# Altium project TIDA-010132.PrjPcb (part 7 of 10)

## Sheet USB INTERFACE SHEET.SchDoc
size 558 x 431 mm; Date: Not shown in title block; ApprovedBy: Not shown in title block; CheckedBy: Not shown in title block; Author: Not shown in title block; CompanyName: Not shown in title block; DrawnBy: Avinash N; Engineer: Not shown in title block; Organization: Not shown in title block; Address1: Not shown in title block; Address2: Not shown in title block; Address3: Not shown in title block; Address4: Not shown in title block; DocumentNumber: 1; Revision: Use project parameter SCH_Rev; SheetNumber: 27; SheetTotal: 32; PageSetup: Record=PageOptions¦CenterHorizontal=True¦CenterVertical=True¦PrintScale=1.00¦XCorrection=1.00¦YCorrection=1.00¦PrintKind=0¦BorderSize=5000000¦LeftOffset=0¦BottomOffset=0¦Orientation=2¦PaperLength=1000¦PaperWidth=1000¦Scale=100¦PaperSource=15¦PrintQuality=600¦MediaType=1¦DitherType=10¦PaperKind=Letter¦PrintScaleMode=1
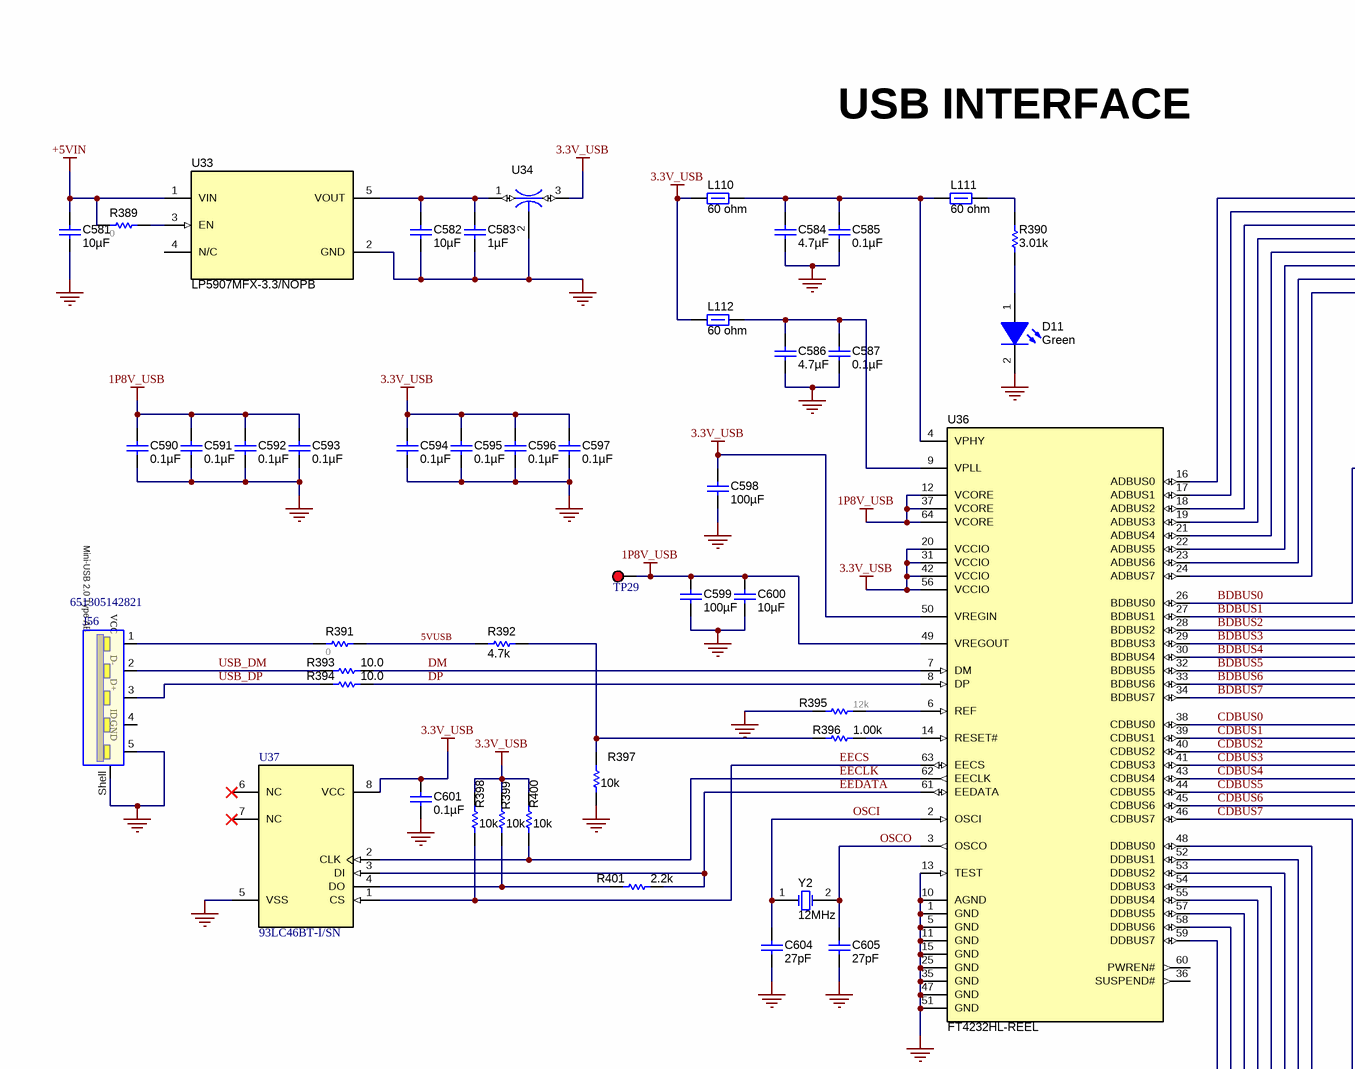
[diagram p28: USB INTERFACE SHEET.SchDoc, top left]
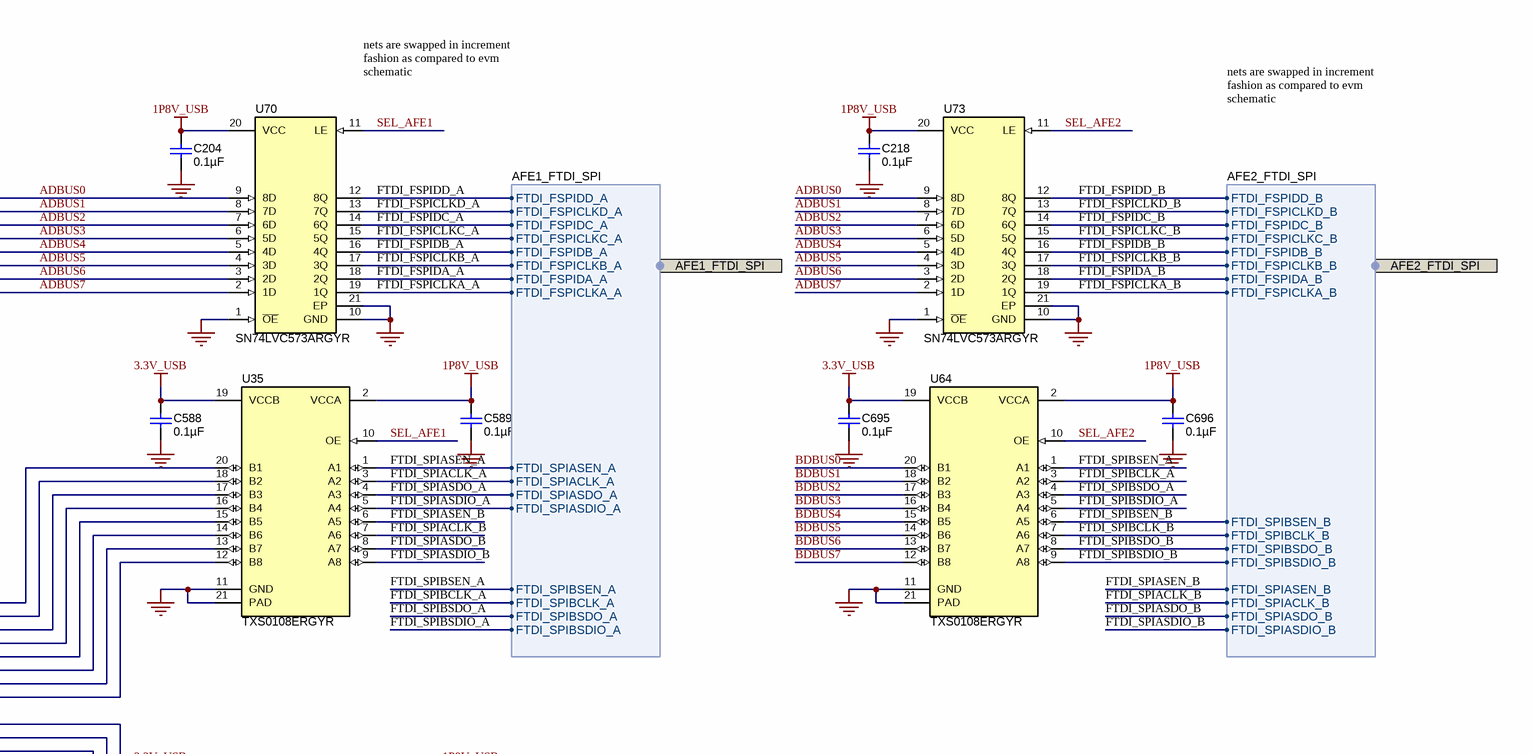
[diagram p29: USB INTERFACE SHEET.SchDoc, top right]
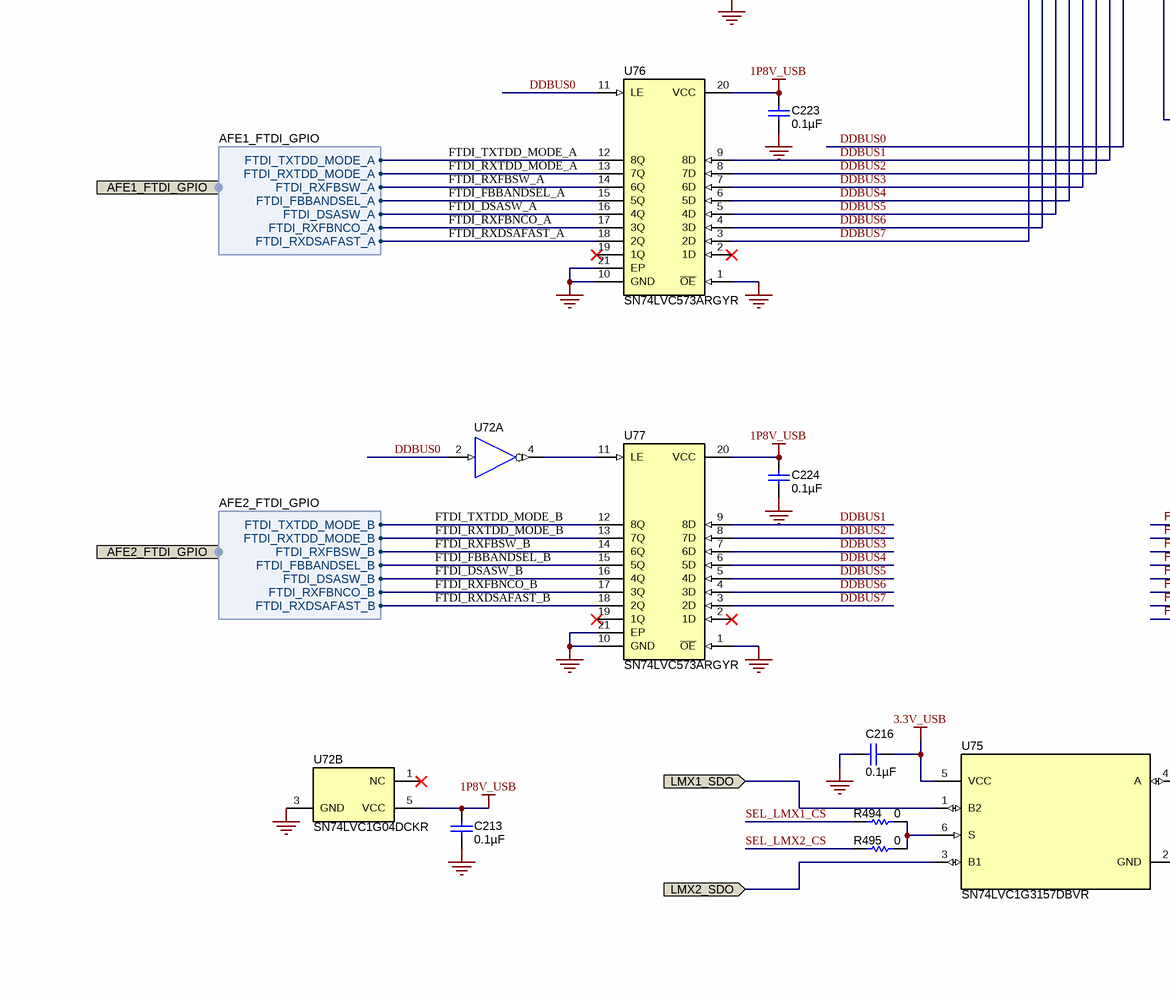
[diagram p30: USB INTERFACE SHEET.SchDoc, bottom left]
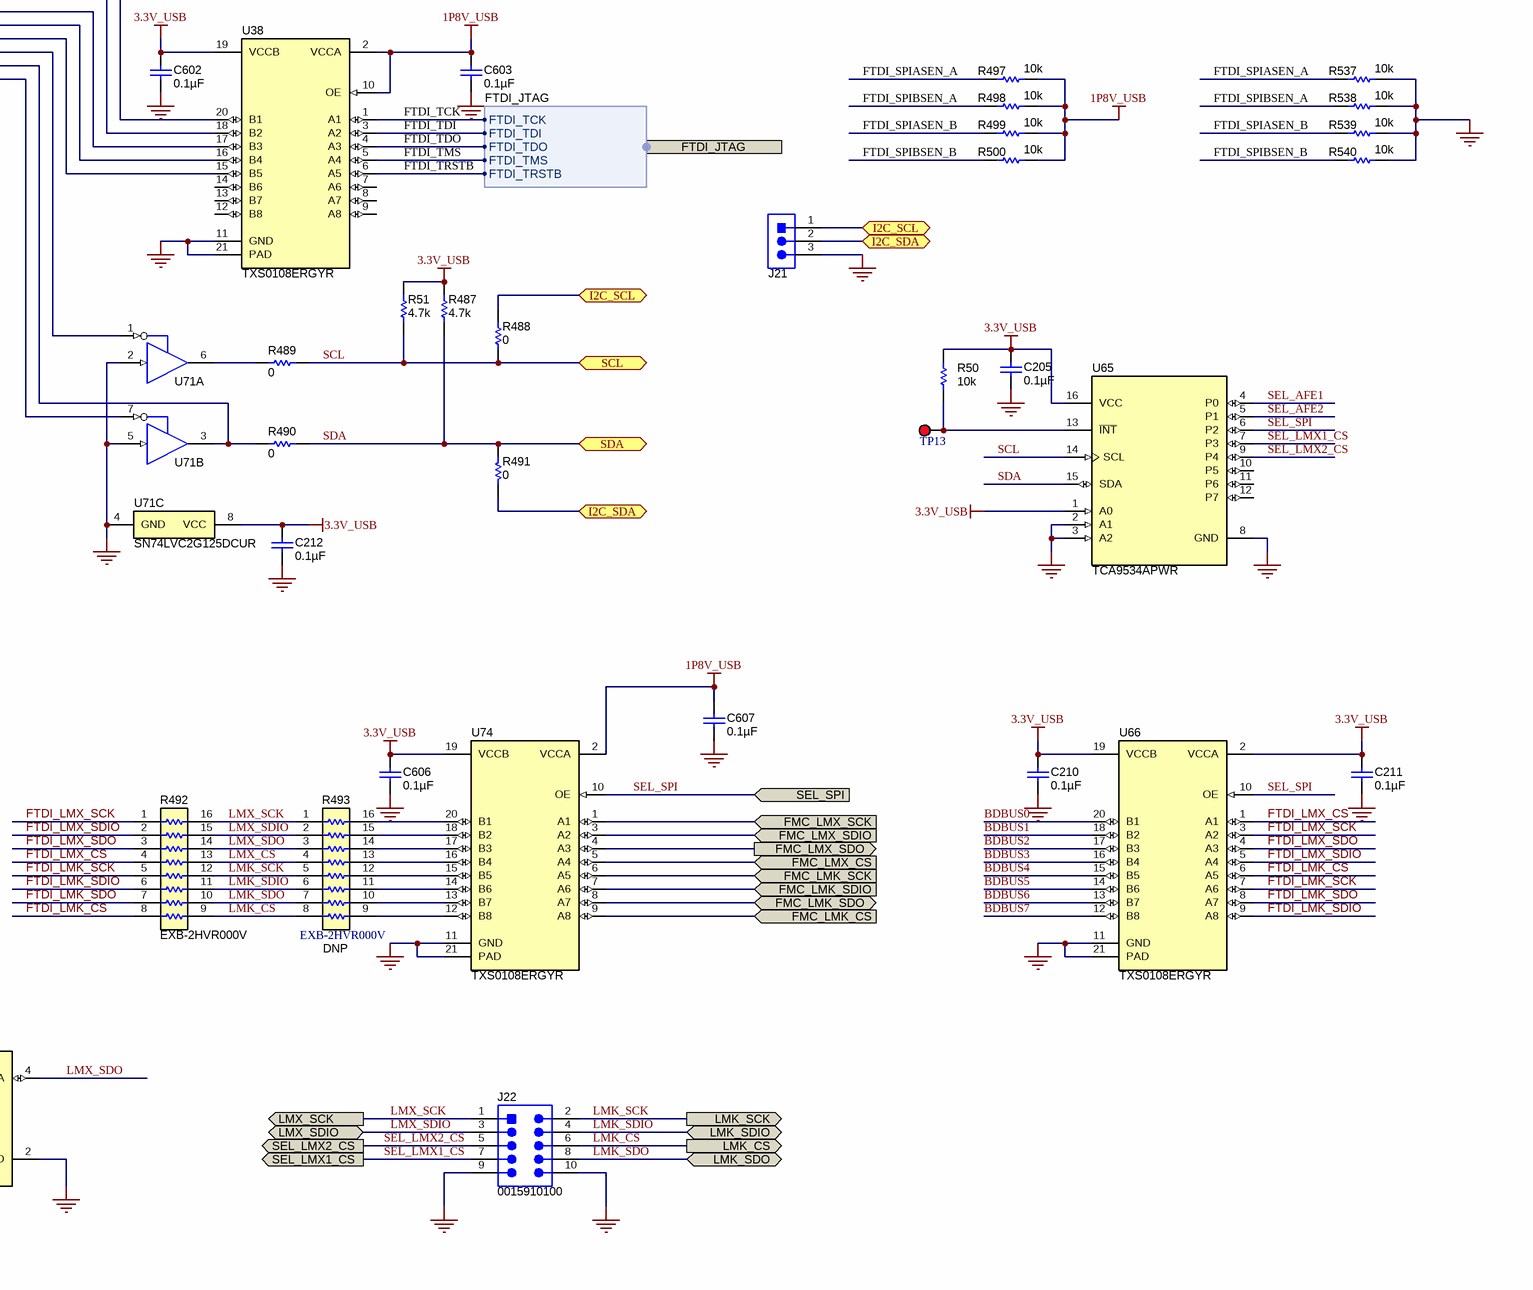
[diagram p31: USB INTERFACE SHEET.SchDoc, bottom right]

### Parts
C204  ValueDisplayed: 0.1µF  [0603]  (hidden comment: C0603C104J3RACTU)
C205  ValueDisplayed: 0.1µF  [0603]  (hidden comment: C0603C104J3RACTU)
C210  ValueDisplayed: 0.1µF  [0603]  (hidden comment: C0603C104J3RACTU)
C211  ValueDisplayed: 0.1µF  [0603]  (hidden comment: C0603C104J3RACTU)
C212  ValueDisplayed: 0.1µF  [0603]  (hidden comment: C0603C104J3RACTU)
C213  ValueDisplayed: 0.1µF  [0603]  (hidden comment: C0603C104J3RACTU)
C216  ValueDisplayed: 0.1µF  [0603]  (hidden comment: C0603C104J3RACTU)
C218  ValueDisplayed: 0.1µF  [0603]  (hidden comment: C0603C104J3RACTU)
C223  ValueDisplayed: 0.1µF  [0603]  (hidden comment: C0603C104J3RACTU)
C224  ValueDisplayed: 0.1µF  [0603]  (hidden comment: C0603C104J3RACTU)
C581  ValueDisplayed: 10µF  [0603]  (hidden comment: GRM188R61A106ME69D)
C582  ValueDisplayed: 10µF  [0603]  (hidden comment: GRM188R61A106ME69D)
C583  ValueDisplayed: 1µF  [0603]  (hidden comment: C1608X7R1C105K080AC)
C584  ValueDisplayed: 4.7µF  [0805_HV]  (hidden comment: 885012207025)
C585  ValueDisplayed: 0.1µF  [0603]  (hidden comment: C0603C104J3RACTU)
C586  ValueDisplayed: 4.7µF  [0805_HV]  (hidden comment: 885012207025)
C587  ValueDisplayed: 0.1µF  [0603]  (hidden comment: C0603C104J3RACTU)
C588  ValueDisplayed: 0.1µF  [0603]  (hidden comment: C0603C104J3RACTU)
C589  ValueDisplayed: 0.1µF  [0603]  (hidden comment: C0603C104J3RACTU)
C590  ValueDisplayed: 0.1µF  [0603]  (hidden comment: C0603C104J3RACTU)
C591  ValueDisplayed: 0.1µF  [0603]  (hidden comment: C0603C104J3RACTU)
C592  ValueDisplayed: 0.1µF  [0603]  (hidden comment: C0603C104J3RACTU)
C593  ValueDisplayed: 0.1µF  [0603]  (hidden comment: C0603C104J3RACTU)
C594  ValueDisplayed: 0.1µF  [0603]  (hidden comment: C0603C104J3RACTU)
C595  ValueDisplayed: 0.1µF  [0603]  (hidden comment: C0603C104J3RACTU)
C596  ValueDisplayed: 0.1µF  [0603]  (hidden comment: C0603C104J3RACTU)
C597  ValueDisplayed: 0.1µF  [0603]  (hidden comment: C0603C104J3RACTU)
C598  ValueDisplayed: 100µF  [1210_270]  (hidden comment: GRM32ER61A107ME20L)
C599  ValueDisplayed: 100µF  [1210_270]  (hidden comment: GRM32ER61A107ME20L)
C600  ValueDisplayed: 10µF  [0603]  (hidden comment: GRM188R61A106ME69D)
C601  ValueDisplayed: 0.1µF  [0603]  (hidden comment: C0603C104J3RACTU)
C602  ValueDisplayed: 0.1µF  [0603]  (hidden comment: C0603C104J3RACTU)
C603  ValueDisplayed: 0.1µF  [0603]  (hidden comment: C0603C104J3RACTU)
C604  ValueDisplayed: 27pF  [0603]  (hidden comment: CL10C270FB8NNNC)
C605  ValueDisplayed: 27pF  [0603]  (hidden comment: CL10C270FB8NNNC)
C606  ValueDisplayed: 0.1µF  [0603]  (hidden comment: C0603C104J3RACTU)
C607  ValueDisplayed: 0.1µF  [0603]  (hidden comment: C0603C104J3RACTU)
C695  ValueDisplayed: 0.1µF  [0603]  (hidden comment: C0603C104J3RACTU)
C696  ValueDisplayed: 0.1µF  [0603]  (hidden comment: C0603C104J3RACTU)
D11  value Green  [LTST-C191_Green]  (hidden comment: LTST-C191TGKT)
J21  800-10-003-10-001000  [Mill-Max_800-10-003-10-001000]  (value not drawn)
J22  0015910100  [Molex_0015910100]
J56  651305142821  [651305142821]
L110  ValueDisplayed: 60 ohm  [0603]  (hidden comment: MPZ1608S600ATAH0)
L111  ValueDisplayed: 60 ohm  [0603]  (hidden comment: MPZ1608S600ATAH0)
L112  ValueDisplayed: 60 ohm  [0603]  (hidden comment: MPZ1608S600ATAH0)
R50  ValueDisplayed: 10k  [0603]  (hidden comment: CRCW060310K0JNEA)
R51  ValueDisplayed: 4.7k  [0603]  (hidden comment: CRCW06034K70JNEA)
R389  value 0  [0603]  (hidden comment: CRCW06030000Z0EA)
R390  ValueDisplayed: 3.01k  [0603]  (hidden comment: RC0603FR-073K01L)
R391  value 0  [0603]  (hidden comment: CRCW06030000Z0EA)
R392  ValueDisplayed: 4.7k  [0603]  (hidden comment: RC0603JR-074K7L)
R393  ValueDisplayed: 10.0  [0603]  (hidden comment: CRCW060310R0FKEAHP)
R394  ValueDisplayed: 10.0  [0603]  (hidden comment: CRCW060310R0FKEAHP)
R395  value 12k  [0603]  (hidden comment: CRCW060312K0JNEA)
R396  ValueDisplayed: 1.00k  [0603]  (hidden comment: CRCW06031K00FKEA)
R397  ValueDisplayed: 10k  [0603]  (hidden comment: CRCW060310K0JNEA)
R398  ValueDisplayed: 10k  [0603]  (hidden comment: CRCW060310K0JNEA)
R399  ValueDisplayed: 10k  [0603]  (hidden comment: CRCW060310K0JNEA)
R400  ValueDisplayed: 10k  [0603]  (hidden comment: CRCW060310K0JNEA)
R401  ValueDisplayed: 2.2k  [0603]  (hidden comment: CRCW06032K20JNEA)
R487  ValueDisplayed: 4.7k  [0603]  (hidden comment: CRCW06034K70JNEA)
R488  ValueDisplayed: 0  [0603]  (hidden comment: CRCW06030000Z0EA)
R489  ValueDisplayed: 0  [0603]  (hidden comment: CRCW06030000Z0EA)
R490  ValueDisplayed: 0  [0603]  (hidden comment: CRCW06030000Z0EA)
R491  ValueDisplayed: 0  [0603]  (hidden comment: CRCW06030000Z0EA)
R492  EXB-2HVR000V  [RESCAXS_EXB-2HV]
R493  DNP  PartNumber: EXB-2HVR000V  [RESCAXS_EXB-2HV]
R494  ValueDisplayed: 0  [0603]  (hidden comment: CRCW06030000Z0EA)
R495  ValueDisplayed: 0  [0603]  (hidden comment: CRCW06030000Z0EA)
R497  ValueDisplayed: 10k  [0603]  (hidden comment: CRCW060310K0JNEA)
R498  ValueDisplayed: 10k  [0603]  (hidden comment: CRCW060310K0JNEA)
R499  ValueDisplayed: 10k  [0603]  (hidden comment: CRCW060310K0JNEA)
R500  ValueDisplayed: 10k  [0603]  (hidden comment: CRCW060310K0JNEA)
R537  ValueDisplayed: 10k  [0603]  (hidden comment: CRCW060310K0JNEA)
R538  ValueDisplayed: 10k  [0603]  (hidden comment: CRCW060310K0JNEA)
R539  ValueDisplayed: 10k  [0603]  (hidden comment: CRCW060310K0JNEA)
R540  ValueDisplayed: 10k  [0603]  (hidden comment: CRCW060310K0JNEA)
TP13  5000  [Keystone5000]  (value not drawn)
TP29  5000  [Keystone5000]  (value not drawn)
U33  LP5907MFX-3.3/NOPB  [DBV0005A_N]
U34  NFM31PC276B0J3L  [Murata_NFM31P]  (value not drawn)
U35  TXS0108ERGYR  [RGY0020A]
U36  FT4232HL-REEL  [LQFP64_N]
U37  93LC46BT-I/SN  [SOIC-8]
U38  TXS0108ERGYR  [RGY0020A]
U64  TXS0108ERGYR  [RGY0020A]
U65  TCA9534APWR  [PW0016A_N]
U66  TXS0108ERGYR  [RGY0020A]
U70  SN74LVC573ARGYR  [RGY0020A]
U71  SN74LVC2G125DCUR  [DCU0008A_N]  (value not drawn)  (parts A,B,C of 3)
U72  SN74LVC1G04DCKR  [DCK0005A_N]  (value not drawn)  (parts A,B of 2)
U73  SN74LVC573ARGYR  [RGY0020A]
U74  TXS0108ERGYR  [RGY0020A]
U75  SN74LVC1G3157DBVR  [DBV0006A_N]
U76  SN74LVC573ARGYR  [RGY0020A]
U77  SN74LVC573ARGYR  [RGY0020A]
Y2  Frequency: 12MHz  [XTAL_ABM3]  (hidden comment: ABM3-12.000MHZ-D2Y-T)

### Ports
AFE1_FTDI_GPIO (harness AFE1_FTDI_GPIO), AFE1_FTDI_SPI (harness AFE1_FTDI_SPI), AFE2_FTDI_GPIO (harness AFE2_FTDI_GPIO), AFE2_FTDI_SPI (harness AFE2_FTDI_SPI), FMC_LMK_CS (in), FMC_LMK_SCK (in), FMC_LMK_SDIO (in), FMC_LMK_SDO (bidir), FMC_LMX_CS (in), FMC_LMX_SCK (in), FMC_LMX_SDIO (in), FMC_LMX_SDO (out), FTDI_JTAG (harness FTDI_JTAG), I2C_SCL (bidir), I2C_SDA (bidir), LMK_CS (out), LMK_SCK (out), LMK_SDIO (bidir), LMK_SDO (bidir), LMX1_SDO (in), LMX2_SDO (in), LMX_SCK (out), LMX_SDIO (bidir), SCL (bidir), SDA (bidir), SEL_LMX1_CS (out), SEL_LMX2_CS (out), SEL_SPI (in)

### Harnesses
AFE2_FTDI_GPIO: FTDI_FBBANDSEL_B, FTDI_RXFBSW_B, FTDI_RXTDD_MODE_B, FTDI_TXTDD_MODE_B, FTDI_DSASW_B, FTDI_RXFBNCO_B, FTDI_RXDSAFAST_B
AFE1_FTDI_GPIO: FTDI_FBBANDSEL_A, FTDI_RXFBSW_A, FTDI_RXTDD_MODE_A, FTDI_TXTDD_MODE_A, FTDI_DSASW_A, FTDI_RXFBNCO_A, FTDI_RXDSAFAST_A
FTDI_JTAG: FTDI_TCK, FTDI_TDI, FTDI_TDO, FTDI_TMS, FTDI_TRSTB
AFE1_FTDI_SPI: FTDI_FSPICLKA_A, FTDI_FSPIDA_A, FTDI_FSPICLKB_A, FTDI_FSPIDB_A, FTDI_FSPICLKC_A, FTDI_FSPIDC_A, FTDI_FSPICLKD_A, FTDI_FSPIDD_A, FTDI_SPIASEN_A, FTDI_SPIACLK_A, FTDI_SPIASDO_A, FTDI_SPIASDIO_A, FTDI_SPIBSEN_A, FTDI_SPIBCLK_A, FTDI_SPIBSDO_A, FTDI_SPIBSDIO_A
AFE2_FTDI_SPI: FTDI_FSPICLKA_B, FTDI_FSPIDA_B, FTDI_FSPICLKB_B, FTDI_FSPIDB_B, FTDI_FSPICLKC_B, FTDI_FSPIDC_B, FTDI_FSPICLKD_B, FTDI_FSPIDD_B, FTDI_SPIASEN_B, FTDI_SPIACLK_B, FTDI_SPIASDO_B, FTDI_SPIASDIO_B, FTDI_SPIBSEN_B, FTDI_SPIBCLK_B, FTDI_SPIBSDO_B, FTDI_SPIBSDIO_B

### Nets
1P8V_USB: C204.2 C213.2 C218.2 C223.2 C224.2 C589.2 C590.2 C591.2 C592.2 C593.2 C599.1 C600.1 C603.2 C607.2 C696.2 R497.1 R498.1 R499.1 R500.1 TP29.1 U35.2(VCCA) U36.12(VCORE) U36.37(VCORE) U36.49(VREGOUT) U36.64(VCORE) U38.2(VCCA) U38.10(OE) U64.2(VCCA) U70.20(VCC) U72.5(VCC) U73.20(VCC) U74.2(VCCA) U76.20(VCC) U77.20(VCC)
3.3V_USB: C205.2 C210.2 C211.2 C212.2 C216.1 C588.2 C594.2 C595.2 C596.2 C597.2 C598.1 C601.2 C602.2 C606.2 C695.2 L110.1 L112.1 R50.2 R51.2 R398.2 R399.2 R400.2 R487.2 U34.3 U35.19(VCCB) U36.20(VCCIO) U36.31(VCCIO) U36.42(VCCIO) U36.50(VREGIN) U36.56(VCCIO) U37.8(VCC) U38.19(VCCB) U64.19(VCCB) U65.1(A0) U65.16(VCC) U66.2(VCCA) U66.19(VCCB) U71.8(VCC) U74.19(VCCB) U75.5(VCC)
+5VIN: C581.1 R389.1 U33.1(VIN)
GND: C204.1 C205.1 C210.1 C211.1 C212.1 C213.1 C216.2 C218.1 C223.1 C224.1 C581.2 C582.2 C583.2 C584.2 C585.1 C586.2 C587.1 C588.1 C589.1 C590.1 C591.1 C592.1 C593.1 C594.1 C595.1 C596.1 C597.1 C598.2 C599.2 C600.2 C601.1 C602.1 C603.1 C604.2 C605.2 C606.1 C607.1 C695.1 C696.1 D11.2(K) J21.3 J22.9 J22.10 J56.5(GND) J56.Shell R395.2 R397.1 R537.1 R538.1 R539.1 R540.1 U33.2(GND) U34.2 U35.11(GND) U35.21(PAD) U36.1(GND) U36.5(GND) U36.10(AGND) U36.11(GND) U36.13(TEST) U36.15(GND) U36.25(GND) U36.35(GND) U36.47(GND) U36.51(GND) U37.5(VSS) U38.11(GND) U38.21(PAD) U64.11(GND) U64.21(PAD) U65.2(A1) U65.3(A2) U65.8(GND) U66.11(GND) U66.21(PAD) U70.1(~{OE}) U70.10(GND) U70.21(EP) U71.2(1A) U71.4(GND) U71.5(2A) U72.3(GND) U73.1(~{OE}) U73.10(GND) U73.21(EP) U74.11(GND) U74.21(PAD) U75.2(GND) U76.1(~{OE}) U76.10(GND) U76.21(EP) U77.1(~{OE}) U77.10(GND) U77.21(EP)
5VUSB: R391.2 R392.1
ADBUS0: U36.16(ADBUS0) U70.9(8D) U73.9(8D)
ADBUS1: U36.17(ADBUS1) U70.8(7D) U73.8(7D)
ADBUS2: U36.18(ADBUS2) U70.7(6D) U73.7(6D)
ADBUS3: U36.19(ADBUS3) U70.6(5D) U73.6(5D)
ADBUS4: U36.21(ADBUS4) U70.5(4D) U73.5(4D)
ADBUS5: U36.22(ADBUS5) U70.4(3D) U73.4(3D)
ADBUS6: U36.23(ADBUS6) U70.3(2D) U73.3(2D)
ADBUS7: U36.24(ADBUS7) U70.2(1D) U73.2(1D)
BDBUS0: U35.20(B1) U36.26(BDBUS0) U64.20(B1) U66.20(B1)
BDBUS1: U35.18(B2) U36.27(BDBUS1) U64.18(B2) U66.18(B2)
BDBUS2: U35.17(B3) U36.28(BDBUS2) U64.17(B3) U66.17(B3)
BDBUS3: U35.16(B4) U36.29(BDBUS3) U64.16(B4) U66.16(B4)
BDBUS4: U35.15(B5) U36.30(BDBUS4) U64.15(B5) U66.15(B5)
BDBUS5: U35.14(B6) U36.32(BDBUS5) U64.14(B6) U66.14(B6)
BDBUS6: U35.13(B7) U36.33(BDBUS6) U64.13(B7) U66.13(B7)
BDBUS7: U35.12(B8) U36.34(BDBUS7) U64.12(B8) U66.12(B8)
CDBUS0: U36.38(CDBUS0) U38.20(B1)
CDBUS1: U36.39(CDBUS1) U38.18(B2)
CDBUS2: U36.40(CDBUS2) U38.17(B3)
CDBUS3: U36.41(CDBUS3) U38.16(B4)
CDBUS4: U36.43(CDBUS4) U38.15(B5)
CDBUS5: U36.44(CDBUS5) U71.1(1~{OE})
CDBUS6: R490.2 U36.45(CDBUS6) U71.3(2Y)
CDBUS7: U36.46(CDBUS7) U71.7(2~{OE})
DDBUS0: U36.48(DDBUS0) U72.2(A) U76.11(LE)
DDBUS1: U36.52(DDBUS1) U76.9(8D) U77.9(8D)
DDBUS2: U36.53(DDBUS2) U76.8(7D) U77.8(7D)
DDBUS3: U36.54(DDBUS3) U76.7(6D) U77.7(6D)
DDBUS4: U36.55(DDBUS4) U76.6(5D) U77.6(5D)
DDBUS5: U36.57(DDBUS5) U76.5(4D) U77.5(4D)
DDBUS6: U36.58(DDBUS6) U76.4(3D) U77.4(3D)
DDBUS7: U36.59(DDBUS7) U76.3(2D) U77.3(2D)
DM: R393.2 U36.7(DM)
DP: R394.2 U36.8(DP)
EECLK: R400.1 U36.62(EECLK) U37.2(CLK)
EECS: R398.1 U36.63(EECS) U37.1(CS)
EEDATA: R401.2 U36.61(EEDATA) U37.3(DI)
FMC_LMK_CS: U74.9(A8) ; port FMC_LMK_CS
FMC_LMK_SCK: U74.6(A5) ; port FMC_LMK_SCK
FMC_LMK_SDIO: U74.7(A6) ; port FMC_LMK_SDIO
FMC_LMK_SDO: U74.8(A7) ; port FMC_LMK_SDO
FMC_LMX_CS: U74.5(A4) ; port FMC_LMX_CS
FMC_LMX_SCK: U74.1(A1) ; port FMC_LMX_SCK
FMC_LMX_SDIO: U74.3(A2) ; port FMC_LMX_SDIO
FMC_LMX_SDO: U74.4(A3) ; port FMC_LMX_SDO
FTDI_DSASW_A: U76.16(4Q) ; port AFE1_FTDI_GPIO.FTDI_DSASW_A
FTDI_DSASW_B: U77.16(4Q) ; port AFE2_FTDI_GPIO.FTDI_DSASW_B
FTDI_FBBANDSEL_A: U76.15(5Q) ; port AFE1_FTDI_GPIO.FTDI_FBBANDSEL_A
FTDI_FBBANDSEL_B: U77.15(5Q) ; port AFE2_FTDI_GPIO.FTDI_FBBANDSEL_B
FTDI_FSPICLKA_A: U70.19(1Q) ; port AFE1_FTDI_SPI.FTDI_FSPICLKA_A
FTDI_FSPICLKA_B: U73.19(1Q) ; port AFE2_FTDI_SPI.FTDI_FSPICLKA_B
FTDI_FSPICLKB_A: U70.17(3Q) ; port AFE1_FTDI_SPI.FTDI_FSPICLKB_A
FTDI_FSPICLKB_B: U73.17(3Q) ; port AFE2_FTDI_SPI.FTDI_FSPICLKB_B  [project net FTDI_FSPICLKB]
FTDI_FSPICLKC_A: U70.15(5Q) ; port AFE1_FTDI_SPI.FTDI_FSPICLKC_A
FTDI_FSPICLKC_B: U73.15(5Q) ; port AFE2_FTDI_SPI.FTDI_FSPICLKC_B
FTDI_FSPICLKD_A: U70.13(7Q) ; port AFE1_FTDI_SPI.FTDI_FSPICLKD_A
FTDI_FSPICLKD_B: U73.13(7Q) ; port AFE2_FTDI_SPI.FTDI_FSPICLKD_B
FTDI_FSPIDA_A: U70.18(2Q) ; port AFE1_FTDI_SPI.FTDI_FSPIDA_A
FTDI_FSPIDA_B: U73.18(2Q) ; port AFE2_FTDI_SPI.FTDI_FSPIDA_B
FTDI_FSPIDB_A: U70.16(4Q) ; port AFE1_FTDI_SPI.FTDI_FSPIDB_A
FTDI_FSPIDB_B: U73.16(4Q) ; port AFE2_FTDI_SPI.FTDI_FSPIDB_B
FTDI_FSPIDC_A: U70.14(6Q) ; port AFE1_FTDI_SPI.FTDI_FSPIDC_A
FTDI_FSPIDC_B: U73.14(6Q) ; port AFE2_FTDI_SPI.FTDI_FSPIDC_B
FTDI_FSPIDD_A: U70.12(8Q) ; port AFE1_FTDI_SPI.FTDI_FSPIDD_A
FTDI_FSPIDD_B: U73.12(8Q) ; port AFE2_FTDI_SPI.FTDI_FSPIDD_B
FTDI_LMK_CS: R492.8 U66.6(A5)
FTDI_LMK_SCK: R492.5 U66.7(A6)
FTDI_LMK_SDIO: R492.6 U66.9(A8)
FTDI_LMK_SDO: R492.7 U66.8(A7)
FTDI_LMX_CS: R492.4 U66.1(A1)
FTDI_LMX_SCK: R492.1 U66.3(A2)
FTDI_LMX_SDIO: R492.2 U66.5(A4)
FTDI_LMX_SDO: R492.3 U66.4(A3)
FTDI_RXDSAFAST_A: U76.18(2Q) ; port AFE1_FTDI_GPIO.FTDI_RXDSAFAST_A
FTDI_RXDSAFAST_B: U77.18(2Q) ; port AFE2_FTDI_GPIO.FTDI_RXDSAFAST_B
FTDI_RXFBNCO_A: U76.17(3Q) ; port AFE1_FTDI_GPIO.FTDI_RXFBNCO_A
FTDI_RXFBNCO_B: U77.17(3Q) ; port AFE2_FTDI_GPIO.FTDI_RXFBNCO_B
FTDI_RXFBSW_A: U76.14(6Q) ; port AFE1_FTDI_GPIO.FTDI_RXFBSW_A
FTDI_RXFBSW_B: U77.14(6Q) ; port AFE2_FTDI_GPIO.FTDI_RXFBSW_B
FTDI_RXTDD_MODE_A: U76.13(7Q) ; port AFE1_FTDI_GPIO.FTDI_RXTDD_MODE_A
FTDI_RXTDD_MODE_B: U77.13(7Q) ; port AFE2_FTDI_GPIO.FTDI_RXTDD_MODE_B
FTDI_SPIACLK_A: U35.3(A2) ; port AFE1_FTDI_SPI.FTDI_SPIACLK_A
FTDI_SPIACLK_B: U35.7(A6) ; port AFE2_FTDI_SPI.FTDI_SPIACLK_B
FTDI_SPIASDIO_A: U35.5(A4) ; port AFE1_FTDI_SPI.FTDI_SPIASDIO_A
FTDI_SPIASDIO_B: U35.9(A8) ; port AFE2_FTDI_SPI.FTDI_SPIASDIO_B
FTDI_SPIASDO_A: U35.4(A3) ; port AFE1_FTDI_SPI.FTDI_SPIASDO_A
FTDI_SPIASDO_B: U35.8(A7) ; port AFE2_FTDI_SPI.FTDI_SPIASDO_B
FTDI_SPIASEN_A: R497.2 R537.2 U35.1(A1) ; port AFE1_FTDI_SPI.FTDI_SPIASEN_A
FTDI_SPIASEN_B: R499.2 R539.2 U35.6(A5) ; port AFE2_FTDI_SPI.FTDI_SPIASEN_B
FTDI_SPIBCLK_A: U64.3(A2) ; port AFE1_FTDI_SPI.FTDI_SPIBCLK_A
FTDI_SPIBCLK_B: U64.7(A6) ; port AFE2_FTDI_SPI.FTDI_SPIBCLK_B
FTDI_SPIBSDIO_A: U64.5(A4) ; port AFE1_FTDI_SPI.FTDI_SPIBSDIO_A
FTDI_SPIBSDIO_B: U64.9(A8) ; port AFE2_FTDI_SPI.FTDI_SPIBSDIO_B
FTDI_SPIBSDO_A: U64.4(A3) ; port AFE1_FTDI_SPI.FTDI_SPIBSDO_A
FTDI_SPIBSDO_B: U64.8(A7) ; port AFE2_FTDI_SPI.FTDI_SPIBSDO_B
FTDI_SPIBSEN_A: R498.2 R538.2 U64.1(A1) ; port AFE1_FTDI_SPI.FTDI_SPIBSEN_A
FTDI_SPIBSEN_B: R500.2 R540.2 U64.6(A5) ; port AFE2_FTDI_SPI.FTDI_SPIBSEN_B
FTDI_TCK: U38.1(A1) ; port FTDI_JTAG.FTDI_TCK
FTDI_TDI: U38.3(A2) ; port FTDI_JTAG.FTDI_TDI
FTDI_TDO: U38.4(A3) ; port FTDI_JTAG.FTDI_TDO
FTDI_TMS: U38.5(A4) ; port FTDI_JTAG.FTDI_TMS
FTDI_TRSTB: U38.6(A5) ; port FTDI_JTAG.FTDI_TRSTB
FTDI_TXTDD_MODE_A: U76.12(8Q) ; port AFE1_FTDI_GPIO.FTDI_TXTDD_MODE_A
FTDI_TXTDD_MODE_B: U77.12(8Q) ; port AFE2_FTDI_GPIO.FTDI_TXTDD_MODE_B
I2C_SCL: J21.1 R488.1 ; port I2C_SCL
I2C_SDA: J21.2 R491.1 ; port I2C_SDA
LMK_CS: J22.6 R492.9 R493.8 ; port LMK_CS
LMK_SCK: J22.2 R492.12 R493.5 ; port LMK_SCK
LMK_SDIO: J22.4 R492.11 R493.6 ; port LMK_SDIO
LMK_SDO: J22.8 R492.10 R493.7 ; port LMK_SDO
LMX1_SDO: U75.1(B2) ; port LMX1_SDO
LMX2_SDO: U75.3(B1) ; port LMX2_SDO
LMX_CS: R492.13 R493.4
LMX_SCK: J22.1 R492.16 R493.1 ; port LMX_SCK
LMX_SDIO: J22.3 R492.15 R493.2 ; port LMX_SDIO
LMX_SDO: R492.14 R493.3 U75.4(A)
OSCI: C604.1 U36.2(OSCI) Y2.1(OSC1)
OSCO: C605.1 U36.3(OSCO) Y2.2(OSC2)
SCL: R51.1 R488.2 R489.1 U65.14(SCL) ; port SCL
SDA: R487.1 R490.1 R491.2 U65.15(SDA) ; port SDA
SEL_AFE1: U35.10(OE) U65.4(P0) U70.11(LE)
SEL_AFE2: U64.10(OE) U65.5(P1) U73.11(LE)
SEL_LMX1_CS: J22.7 R494.2 U65.7(P3) ; port SEL_LMX1_CS
SEL_LMX2_CS: J22.5 R495.2 U65.9(P4) ; port SEL_LMX2_CS
SEL_SPI: U65.6(P2) U66.10(OE) U74.10(OE) ; port SEL_SPI
USB_DM: J56.2(D-) R393.1
USB_DP: J56.3(D+) R394.1
NetC582_1: C582.1 C583.1 U33.5(VOUT) U34.1
NetC584_1: C584.1 C585.2 L110.2 L111.2 U36.4(VPHY)
NetC586_1: C586.1 C587.2 L112.2 U36.9(VPLL)
NetD11_1: D11.1(A) R390.1
NetJ56_1: J56.1(VCC) R391.1
NetL111_1: L111.1 R390.2
NetR50_1: R50.1 TP13.1 U65.13(~{INT})
NetR389_2: R389.2 U33.3(EN)
NetR392_2: R392.2 R396.1 R397.2
NetR395_1: R395.1 U36.6(REF)
NetR396_2: R396.2 U36.14(RESET#)
NetR399_1: R399.1 R401.1 U37.4(DO)
NetR489_2: R489.2 U71.6(1Y)
NetR493_9: R493.9 U74.12(B8)
NetR493_10: R493.10 U74.13(B7)
NetR493_11: R493.11 U74.14(B6)
NetR493_12: R493.12 U74.15(B5)
NetR493_13: R493.13 U74.16(B4)
NetR493_14: R493.14 U74.17(B3)
NetR493_15: R493.15 U74.18(B2)
NetR493_16: R493.16 U74.20(B1)
NetR494_1: R494.1 R495.1 U75.6(S)
NetU72_4: U72.4(Y) U77.11(LE)

Not connected (* = marked no-connect by the designer): J56 4(ID); U33 4(N/C); U36 36(SUSPEND#) 60(PWREN#); U37 6(NC)* 7(NC)*; U38 7(A6) 8(A7) 9(A8) 12(B8) 13(B7) 14(B6); U65 10(P5) 11(P6) 12(P7); U72 1(NC)*; U76 2(1D)* 19(1Q)*; U77 2(1D)* 19(1Q)*

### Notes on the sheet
- USB INTERFACE
- (near U70) nets are swapped in increment fashion as compared to evm schematic
- nets are swapped in increment fashion as compared to evm schematic

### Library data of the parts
C204 C205 C210-C213 C216 C218 C223 C224 C585 C587-C597 C601-C603 C606 C607 C695 C696 = C0603C104J3RACTU: CAP, CERM, 0.1uF, 25V, +/-5%, X7R, 0603; Manufacturer: Kemet; Polarized: N; TaMax_C: 125; TaMin_C: -55; Tolerance_%: 5; VDC_V: 25; Cap_F: 0.0000001; CompType: Capacitor; Value1: Unknown; U/M: EA
C581 C582 C600 = GRM188R61A106ME69D: CAP, CERM, 10 µF, 10 V, +/- 20%, X5R, 0603; Manufacturer: MuRata; Polarized: N; CompType: Capacitor; Value: 10uF; U/M: EA; Cap_F: 0.00001; Tolerance_%: 20; Value1: Unknown; VDC_V: 10; Value2: 10V; TaMin_C: -55; TaMax_C: 85; SizeArea_mm2: 1.28; SizeAreaWB_mm2: 4.68; SizeX_mm: 1.6; SizeY_mm: 0.8; SizeZ_mm: 1; AEC Category: Q200
C583 = C1608X7R1C105K080AC: CAP, CERM, 1 µF, 16 V, +/- 10%, X7R, 0603; Manufacturer: TDK; Polarized: N; CompType: Capacitor; Value: 1uF; U/M: EA; Cap_F: 0.000001; Tolerance_%: 10; ESR_ohm: 0.0057; Value1: 0.0057 ohm; VDC_V: 16; Value2: 16V; TaMin_C: -55; TaMax_C: 125; SizeArea_mm2: 1.28; SizeAreaWB_mm2: 4.68; SizeX_mm: 1.6; SizeY_mm: 0.8; SizeZ_mm: 1; AEC Category: Q200
C584 C586 = 885012207025: CAP, CERM, 4.7 µF, 10 V,+/- 10%, X7R, 0805; Manufacturer: Wurth Elektronik; Polarized: N; CompType: Capacitor; Value: 4.7uF; U/M: EA; Cap_F: 0.0000047; Tolerance_%: 10; Value2: 10V; TaMin_C: -55; TaMax_C: 125; Cap_Case: 0805; SizeArea_mm2: 2.5; SizeAreaWB_mm2: 6.75; SizeX_mm: 2; SizeY_mm: 1.25; SizeZ_mm: 1.45; AEC Category: Q200
C598 C599 = GRM32ER61A107ME20L: CAP, CERM, 100 µF, 10 V, +/- 20%, X5R, 1210; Manufacturer: MuRata; Polarized: N; CompType: Capacitor; Value: 100uF; U/M: EA; Cap_F: 0.0001; Tolerance_%: 20; Value1: Unknown; VDC_V: 10; Value2: 10V; TaMin_C: -55; TaMax_C: 85; Cap_Case: 1210; SizeArea_mm2: 8; SizeAreaWB_mm2: 14.7; SizeX_mm: 3.2; SizeY_mm: 2.5; SizeZ_mm: 2.7; AEC Category: Q200
C604 C605 = CL10C270FB8NNNC: CAP, CERM, 27 pF, 50 V,+/- 1%, C0G/NP0, 0603; Manufacturer: Samsung Electro-Mechanics; Polarized: N; CompType: Capacitor; Value: 27pF; U/M: EA; Cap_F: 0.000000000027; Tolerance_%: 1; VDC_V: 50; Value2: 50V; TaMin_C: -55; TaMax_C: 125; SizeArea_mm2: 1.28; SizeAreaWB_mm2: 4.68; SizeX_mm: 1.6; SizeY_mm: 0.8; AEC Category: Q200; Green_Lifecycle: Active; Green_REACh: Passed
D11 = LTST-C191TGKT: LED, Green, SMD; Manufacturer: Lite-On; Type: InGaN; Vf_V: 3.2; Value2: 3.2V; Io_A: 0.02; Value1: W; U/M: EA
J21 = 800-10-003-10-001000: Header, 100mil, 3x1, TH; Manufacturer: Mill-Max; SymbolCreator: a0799628
J22 = 0015910100: Header, 100mil, 5x2, SMT; Manufacturer: Molex; SymbolCreator: a0412235; Green_Lifecycle: Active; Green_REACh: Passed
J56 = 651305142821: WR-COM Mini USB 2.0 Type AB SMT Horizontal 5 Contacts
L110-L112 = MPZ1608S600ATAH0: Ferrite Bead, 60 ohm @ 100 MHz, 3.5 A, 0603; Manufacturer: TDK; Value: 60 ohm; Imax_A: 3.5; DCR_ohm: 0.02; Value1: 0.02 ohm; Value2: 3.5A; SizeAreaWB_mm2: 4.68; SizeArea_mm2: 1.28; SizeX_mm: 1.6; SizeY_mm: 0.8; SizeZ_mm: 1; ZTyp@100MHz_Ohm: 60; Green_Lifecycle: Active; Green_REACh: Passed
R50 R397-R400 R497-R500 R537-R540 = CRCW060310K0JNEA: RES, 10 k, 5%, 0.1 W, 0603; Manufacturer: Vishay-Dale; CompType: Resistor; Value: 10k; Res_ohm: 10000; Value_Code: 10k0; Tolerance_%: 5; Power_W: 0.1; Value2: 0.1W; VDC_V: 75; TempCo: 200 ppm/C; SizeArea_mm2: 1.28; SizeX_mm: 1.6; SizeY_mm: 0.8; SizeZ_mm: 1; EIA_Code: E24; U/M: EA; AEC Category: Q200
R51 R487 = CRCW06034K70JNEA: RES, 4.7 k, 5%, 0.1 W, 0603; Manufacturer: Vishay-Dale; CompType: Resistor; Value: 4.7k; Res_ohm: 4700; Value_Code: 4k70; Tolerance_%: 5; Power_W: 0.1; Value2: 0.1W; VDC_V: 75; TempCo: 200 ppm/C; SizeArea_mm2: 1.28; SizeX_mm: 1.6; SizeY_mm: 0.8; SizeZ_mm: 1; EIA_Code: E24; U/M: EA; AEC Category: Q200; Green_Lifecycle: Active; Green_REACh: Passed
R389 R391 = CRCW06030000Z0EA: RES, 0 ohm, 5%, 0.1W, 0603; Manufacturer: Vishay-Dale; CompType: Resistor; Tolerance_%: 5; VDC_V: 75; Power_W: 0.1; U/M: EA; Value_Code: 0000; EIA_Code: E24
R390 = RC0603FR-073K01L: RES, 3.01 k, 1%, 0.1 W, 0603; Manufacturer: Yageo America; CompType: Resistor; Value: 3.01k; Res_ohm: 3010; Value_Code: 3k01; Tolerance_%: 1; Power_W: 0.1; Value2: 0.1W; VDC_V: 150; TempCo: 200 ppm/C; SizeArea_mm2: 1.28; SizeX_mm: 1.6; SizeY_mm: 0.8; EIA_Code: E96; U/M: EA; AEC Category: Q200; Green_Lifecycle: Active; Green_REACh: Passed
R392 = RC0603JR-074K7L: RES, 4.7 k, 5%, 0.1 W, 0603; Manufacturer: Yageo America; CompType: Resistor; Value: 4.7k; Res_ohm: 4700; Value_Code: 4k70; Tolerance_%: 5; Power_W: 0.1; Value2: 0.1W; VDC_V: 50; TempCo: 100 ppm/C; SizeArea_mm2: 1.28; SizeX_mm: 1.6; SizeY_mm: 0.8; SizeZ_mm: 1; EIA_Code: E24; U/M: EA; AEC Category: Q200; Green_Lifecycle: Active; Green_REACh: Passed
R393 R394 = CRCW060310R0FKEAHP: RES, 10.0, 1%, 0.25 W, 0603; Manufacturer: Vishay-Dale; CompType: Resistor; Value: 10.0; Res_ohm: 10; Value_Code: 10R0; Tolerance_%: 1; Power_W: 0.25; Value2: 0.25W; VDC_V: 75; TempCo: 100 ppm/C; SizeArea_mm2: 1.28; SizeX_mm: 1.6; SizeY_mm: 0.8; EIA_Code: E96; U/M: EA; AEC Category: Q200
R395 = CRCW060312K0JNEA: RES, 12k ohm, 5%, 0.1W, 0603; Manufacturer: Vishay-Dale; CompType: Resistor; Tolerance_%: 5; VDC_V: 75; Power_W: 0.1; Res_ohm: 12000; U/M: EA; Value_Code: 12k0; EIA_Code: E24
R396 = CRCW06031K00FKEA: RES, 1.00 k, 1%, 0.1 W, 0603; Manufacturer: Vishay-Dale; CompType: Resistor; Value: 1.00k; Res_ohm: 1000; Value_Code: 1k00; Tolerance_%: 1; Power_W: 0.1; Value2: 0.1W; VDC_V: 75; TempCo: 100 ppm/C; SizeArea_mm2: 1.28; SizeX_mm: 1.6; SizeY_mm: 0.8; EIA_Code: E96; U/M: EA; AEC Category: Q200
R401 = CRCW06032K20JNEA: RES, 2.2 k, 5%, 0.1 W, 0603; Manufacturer: Vishay-Dale; CompType: Resistor; Value: 2.2k; Res_ohm: 2200; Value_Code: 2k20; Tolerance_%: 5; Power_W: 0.1; Value2: 0.1W; VDC_V: 75; TempCo: 200 ppm/C; SizeArea_mm2: 1.28; SizeX_mm: 1.6; SizeY_mm: 0.8; SizeZ_mm: 1; EIA_Code: E24; U/M: EA; AEC Category: Q200
R488-R491 R494 R495 = CRCW06030000Z0EA: RES, 0, 5%, 0.1 W, 0603; Manufacturer: Vishay-Dale; CompType: Resistor; Value: 0; Value_Code: 0000; Tolerance_%: 5; Power_W: 0.1; Value2: 0.1W; VDC_V: 75; TempCo: 200 ppm/C; SizeArea_mm2: 1.28; SizeX_mm: 1.6; SizeY_mm: 0.8; SizeZ_mm: 1; EIA_Code: E24; U/M: EA; AEC Category: Q200
R492 R493 = CMP-0015352-2: RES, 0, 5%, 0.0625 W, Resistor Array - 8x1; Manufacturer: Panasonic; Power_W: 62.5mW; TempCo: ppm/C; Value_Code: 0000; U/M: EA; Value: 0; EIA_Code: E24; AEC Category: Q200
TP13 TP29 = 5000: Test Point, Miniature, Red, TH; Manufacturer: Keystone; CompType: Test Point Loop; ContactFinish: Silver
U33 = CMP-0066020-1: 250-mA Ultra-Low-Noise, Low-IQ LDO, DBV0005A (SOT-23-5); Alternate Manufacturer: Texas Instruments; Green_Lifecycle: Active; SizeAreaWB_mm2: 14.82; Green_REACh: Passed; U/M: EA; SizeZ_mm: 1.45; SizeX_mm: 2.8; SizeY_mm: 2.9; SizeArea_mm2: 8.12; CompType: IC
U34 = CMP-0001934-2: FILTER LC HIGH FREQ 27uF 1206; Manufacturer: MuRata
U35 U38 U64 U66 U74 = CMP-0067446-2: 8-Bit Bidirectional Voltage-Level Shifter For Open-Drain And Push-Pull Application, RGY0020A (VQFN-20); Alternate Manufacturer: Texas Instruments; Green_Lifecycle: Active; SizeAreaWB_mm2: 24.75; Green_REACh: Passed; U/M: EA; SizeZ_mm: 1.0; SizeX_mm: 3.5; SizeY_mm: 4.5; SizeArea_mm2: 15.75; CompType: IC
U36 = FT4232HL: Quad High Speed USB to Multipurpose UART/MPSSE IC; Manufacturer: FTDI; SymbolCreator: a0411947
U37 = 93LC46BT-I/SN: 1K Microwire Compatible Serial EEPROM; Manufacturer: Microchip; SymbolCreator: Altium; SizeAreaWB_mm2: 55.131; SizeArea_mm2: 29.351; SizeX_mm: 5.99; SizeY_mm: 4.9; SizeZ_mm: 1.75
U65 = TCA9534APWR: Remote 8-Bit I2C and Low-Power I/O Expander With Interrupt Output and Configuration Registers, PW0016A (TSSOP-16); Manufacturer: Texas Instruments; SymbolCreator: Altium; SizeArea_mm2: 32; SizeAreaWB_mm2: 58.8; SizeX_mm: 6.4; SizeY_mm: 5; SizeZ_mm: 1.2; CompType: IC; U/M: EA
U70 U73 U76 U77 = SN74LVC573ARGYR: Octal Transparent D-Type Latches With 3-State Outputs, RGY0020A, LARGE T&R; Manufacturer: Texas Instruments; Alternate PartNumber: Equivalent; VCC(Min)(V): 1.65; VCC(Max)(V): 3.6; Output Type: CMOS; Logic: True; Static Current: 0.01; Input Type: CMOS,TTL; Bits(#): 8; F @ Nom Voltage(Max)(Mhz): 100; Rating: Catalog; Technology Family: LVC; Voltage(Nom)(V): 1.8,2.5,2.7,3.3; Schmitt Trigger: No; Output Drive (IOL/IOH)(Max)(mA): 24/-24; Output Logic: Non-inverted; 3-State Output: Yes; tpd @ Nom Voltage(Max)(ns): 19.1,9.6,7.7,6.9
U71 = SN74LVC2G125DCUR: Dual Bus Buffer Gate with 3-State Outputs, DCU0008A, LARGE T&R; Manufacturer: Texas Instruments; Alternate PartNumber: Equivalent; VCC(Min)(V): 1.65; VCC(Max)(V): 5.5; Output Type: CMOS; ICC @ Nom Voltage(Max)(mA): 0.01; Input Type: CMOS/TTL; Bits(#): 2; F @ Nom Voltage(Max)(Mhz): 150; Rating: Catalog; Technology Family: LVC; Voltage(Nom)(V): 1.8,2.5,3.3,5; Schmitt Trigger: No; Output Drive (IOL/IOH)(Max)(mA): 32/-32; tpd @ Nom Voltage(Max)(ns): 9.1,4.8,4.3,3.7; Logic: True; Sub-Family: Non-Inverting Buffer/Driver; 3-State Output: Yes
U72 = SN74LVC1G04DCKR: Single Inverter, DCK0005A, LARGE T&R; Manufacturer: Texas Instruments; Alternate PartNumber: Equivalent; VCC(Min)(V): 1.65; VCC(Max)(V): 5.5; Output Type: CMOS; ICC @ Nom Voltage(Max)(mA): 0.01; Input Type: CMOS/TTL; Bits(#): 1; F @ Nom Voltage(Max)(Mhz): 150; Rating: Catalog; Technology Family: LVC; Voltage(Nom)(V): 1.8,2.5,3.3,5; Schmitt Trigger: No; Output Drive (IOL/IOH)(Max)(mA): 32/-32; tpd @ Nom Voltage(Max)(ns): 7.5,5.2,4.2,3.7; Logic: Inverting; Sub-Family: Inverting Buffer/Driver
U75 = CMP-0050997-2: 1-Channel, 2:1 Analog Switch, DBV0006A (SOT-23-6); Manufacturer: Texas Instruments; Output Type: CMOS; Schmitt Trigger: No; Switch Configuration: SPDT; F @ Nom Voltage(Max)(Mhz): 150; VCC(Min)(V): 1.65; Logic: True; Channels(#): 1; Technology Family: LVC; Input Type: CMOS/TTL; tpd @ Nom Voltage(Max)(ns): 2,1.2,0.8,0.3; ICC @ Nom Voltage(Max)(mA): 0.01; Voltage(Nom)(V): 1.8,2.5,3.3,5; Mux Configuration: 1：2; Output Drive (IOL/IOH)(Max)(mA): 32/-32; VCC(Max)(V): 5.5; Rating: Catalog; AEC Category: Q200; AEC Qualified: N; CompType: IC
Y2 = ABM3-12.000MHZ-D2Y-T: Crystal, 12 MHz, 18 pF, SMD; Manufacturer: Abracon Corporation; SymbolCreator: a0412235; U/M: EA; TaMin_C: -40; TaMax_C: 85; Frequency Stability: ±30ppm

## Sheet AFE2.SchDoc
size 558 x 431 mm; Date: Not shown in title block; ApprovedBy: Not shown in title block; CheckedBy: Not shown in title block; Author: Not shown in title block; CompanyName: Not shown in title block; DrawnBy: Avinash N; Engineer: Not shown in title block; Organization: Not shown in title block; Address1: Not shown in title block; Address2: Not shown in title block; Address3: Not shown in title block; Address4: Not shown in title block; DocumentNumber: 1; Revision: Use project parameter SCH_Rev; SheetNumber: 14; SheetTotal: 32; PageSetup: Record=PageOptions¦CenterHorizontal=True¦CenterVertical=True¦PrintScale=1.00¦XCorrection=1.00¦YCorrection=1.00¦PrintKind=0¦BorderSize=5000000¦LeftOffset=0¦BottomOffset=0¦Orientation=2¦PaperLength=1000¦PaperWidth=1000¦Scale=100¦PaperSource=15¦PrintQuality=600¦MediaType=1¦DitherType=10¦PaperKind=Letter¦PrintScaleMode=1
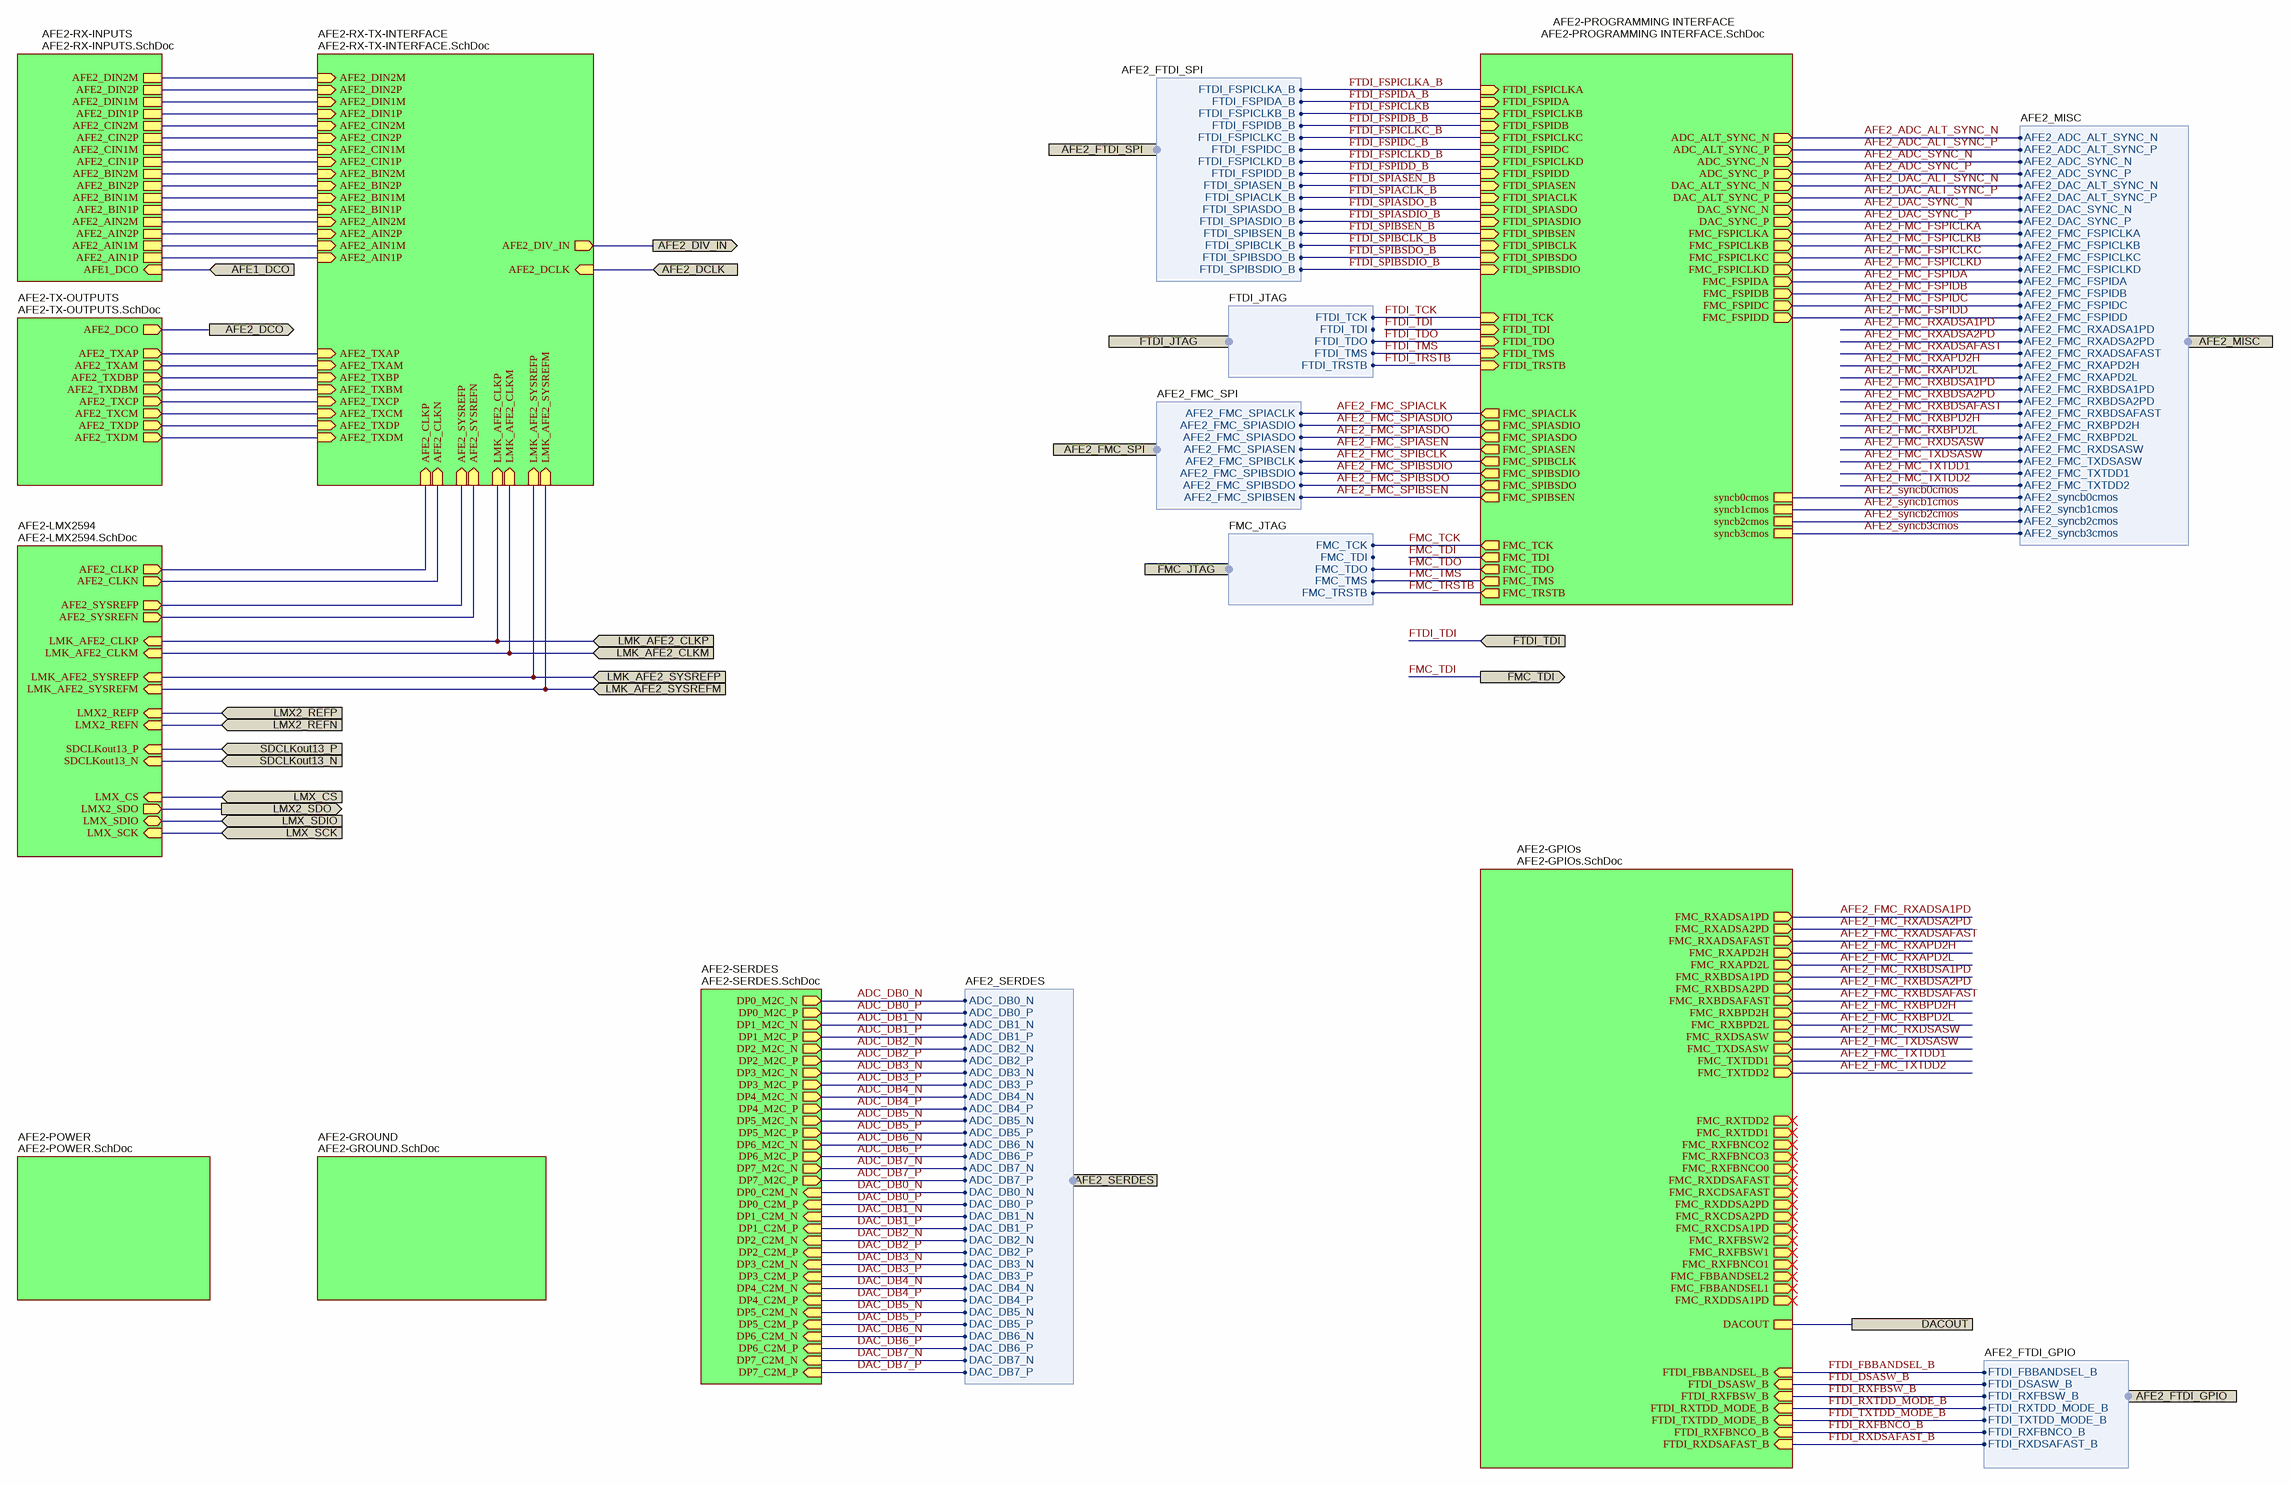
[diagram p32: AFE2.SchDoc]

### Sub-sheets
AFE2-GPIOs = AFE2-GPIOs.SchDoc: FMC_RXADSA1PD (out), FMC_RXADSA2PD (out), FMC_RXADSAFAST (out), FMC_RXAPD2H (out), FMC_RXAPD2L (out), FMC_RXBDSA1PD (out), FMC_RXBDSA2PD (out), FMC_RXBDSAFAST (out), FMC_RXBPD2H (out), FMC_RXBPD2L (out), FMC_RXDSASW (out), FMC_TXDSASW (out), FMC_TXTDD1 (out), FMC_TXTDD2 (out), FMC_RXTDD2 (out), FMC_RXTDD1 (out), FMC_RXFBNCO2 (out), FMC_RXFBNCO3 (out), FMC_RXFBNCO0 (out), FMC_RXDDSAFAST (out), FMC_RXCDSAFAST (out), FMC_RXDDSA2PD (out), FMC_RXCDSA2PD (out), FMC_RXCDSA1PD (out), FMC_RXFBSW2 (out), FMC_RXFBSW1 (out), FMC_RXFBNCO1 (out), FMC_FBBANDSEL2 (out), FMC_FBBANDSEL1 (out), DACOUT, FTDI_RXFBNCO_B (in), FTDI_RXDSAFAST_B (in), FTDI_DSASW_B (in), FTDI_RXFBSW_B (in), FTDI_RXTDD_MODE_B (in), FTDI_TXTDD_MODE_B (in), FTDI_FBBANDSEL_B (in), FMC_RXDDSA1PD (out)
AFE2-GROUND = AFE2-GROUND.SchDoc: no entries
AFE2-LMX2594 = AFE2-LMX2594.SchDoc: AFE2_CLKP (out), AFE2_CLKN (out), AFE2_SYSREFP (out), AFE2_SYSREFN (out), LMK_AFE2_CLKP (in), LMK_AFE2_CLKM (in), SDCLKout13_P (in), SDCLKout13_N (in), LMX2_SDO (out), LMX_CS (in), LMX_SDIO (bidir), LMX_SCK (in), LMK_AFE2_SYSREFM (in), LMK_AFE2_SYSREFP (in), LMX2_REFN (in), LMX2_REFP (in)
AFE2-POWER = AFE2-POWER.SchDoc: no entries
AFE2-PROGRAMMING INTERFACE = AFE2-PROGRAMMING INTERFACE.SchDoc: ADC_ALT_SYNC_P (out), ADC_ALT_SYNC_N (out), ADC_SYNC_P (out), ADC_SYNC_N (out), DAC_ALT_SYNC_P (out), DAC_ALT_SYNC_N (out), DAC_SYNC_P (out), DAC_SYNC_N (out), FMC_FSPICLKA (out), FMC_FSPICLKB (out), FMC_FSPICLKC (out), FMC_FSPICLKD (out), FMC_FSPIDA (out), FMC_FSPIDB (out), FMC_FSPIDC (out), FMC_FSPIDD (out), syncb0cmos, syncb1cmos, syncb2cmos, syncb3cmos, FMC_TMS (out), FMC_TCK (out), FMC_TDO (out), FMC_TDI (out), FMC_TRSTB (out), FMC_SPIASEN (out), FMC_SPIACLK (out), FMC_SPIASDO (out), FMC_SPIASDIO (out), FMC_SPIBSEN (out), FMC_SPIBCLK (out), FMC_SPIBSDO (out), FMC_SPIBSDIO (out), FTDI_TDI (in), FTDI_TDO (in), FTDI_TMS (in), FTDI_TRSTB (in), FTDI_TCK (in), FTDI_FSPIDD (in), FTDI_SPIASEN (in), FTDI_SPIBCLK (in), FTDI_SPIASDIO (in), FTDI_SPIBSEN (in), FTDI_SPIBSDO (in), FTDI_SPIBSDIO (in), FTDI_FSPIDC (in), FTDI_FSPICLKC (in), FTDI_FSPIDB (in), FTDI_FSPICLKB (in), FTDI_FSPIDA (in), FTDI_FSPICLKA (in), FTDI_FSPICLKD (in), FTDI_SPIASDO (in), FTDI_SPIACLK (in)
AFE2-RX-INPUTS = AFE2-RX-INPUTS.SchDoc: AFE2_CIN1M, AFE2_BIN2P, AFE2_AIN2P, AFE2_DIN2P, AFE2_BIN2M, AFE2_CIN1P, AFE2_DIN2M, AFE2_AIN1M, AFE2_DIN1P, AFE2_BIN1M, AFE2_AIN2M, AFE2_DIN1M, AFE2_CIN2P, AFE2_CIN2M, AFE2_AIN1P, AFE2_BIN1P, AFE1_DCO (in)
AFE2-RX-TX-INTERFACE = AFE2-RX-TX-INTERFACE.SchDoc: AFE2_DIN1M (in), AFE2_CIN1M (in), AFE2_BIN1M (in), AFE2_CIN2M (in), AFE2_AIN2M (in), AFE2_DIN2M (in), AFE2_DIN1P (in), AFE2_BIN2P (in), AFE2_CIN1P (in), AFE2_CLKN (in), AFE2_CLKP (in), AFE2_DIV_IN (out), AFE2_SYSREFN (in), AFE2_SYSREFP (in), AFE2_AIN1P (in), AFE2_AIN1M (in), AFE2_DIN2P (in), AFE2_CIN2P (in), AFE2_BIN2M (in), AFE2_BIN1P (in), AFE2_AIN2P (in), LMK_AFE2_SYSREFM (in), LMK_AFE2_SYSREFP (in), LMK_AFE2_CLKP (in), LMK_AFE2_CLKM (in), AFE2_TXAM (in), AFE2_TXAP (in), AFE2_TXBP (in), AFE2_TXBM (in), AFE2_TXCM (in), AFE2_TXCP (in), AFE2_TXDP (in), AFE2_TXDM (in), AFE2_DCLK (in)
AFE2-SERDES = AFE2-SERDES.SchDoc: DP1_M2C_N (out), DP1_M2C_P (out), DP5_C2M_P (in), DP3_M2C_P (out), DP7_M2C_P (out), DP3_M2C_N (out), DP7_M2C_N (out), DP6_M2C_P (out), DP7_C2M_P (in), DP2_M2C_P (out), DP6_C2M_P (in), DP2_M2C_N (out), DP0_M2C_P (out), DP0_M2C_N (out), DP4_C2M_N (in), DP2_C2M_N (in), DP0_C2M_P (in), DP5_M2C_P (out), DP6_C2M_N (in), DP6_M2C_N (out), DP4_C2M_P (in), DP3_C2M_N (in), DP4_M2C_P (out), DP1_C2M_N (in), DP3_C2M_P (in), DP5_M2C_N (out), DP0_C2M_N (in), DP4_M2C_N (out), DP2_C2M_P (in), DP7_C2M_N (in), DP1_C2M_P (in), DP5_C2M_N (in)
AFE2-TX-OUTPUTS = AFE2-TX-OUTPUTS.SchDoc: AFE2_TXAM (out), AFE2_TXAP (out), AFE2_TXDBM (out), AFE2_TXDBP (out), AFE2_TXCM (out), AFE2_TXCP (out), AFE2_TXDM (out), AFE2_TXDP (out), AFE2_DCO (out)

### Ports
AFE1_DCO (in), AFE2_DCLK (in), AFE2_DCO (out), AFE2_DIV_IN (out), AFE2_FMC_SPI (harness AFE2_FMC_SPI), AFE2_FTDI_GPIO (harness AFE2_FTDI_GPIO), AFE2_FTDI_SPI (harness AFE2_FTDI_SPI), AFE2_MISC (harness AFE2_MISC), AFE2_SERDES (harness AFE2_SERDES), DACOUT, FMC_JTAG (harness FMC_JTAG), FMC_TDI (out), FTDI_JTAG (harness FTDI_JTAG), FTDI_TDI (in), LMK_AFE2_CLKM (in), LMK_AFE2_CLKP (in), LMK_AFE2_SYSREFM (in), LMK_AFE2_SYSREFP (in), LMX2_REFN (in), LMX2_REFP (in), LMX2_SDO (out), LMX_CS (in), LMX_SCK (in), LMX_SDIO (in), SDCLKout13_N (in), SDCLKout13_P (in)

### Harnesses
FMC_JTAG: FMC_TCK, FMC_TDI, FMC_TDO, FMC_TMS, FMC_TRSTB
AFE2_FTDI_GPIO: FTDI_FBBANDSEL_B, FTDI_DSASW_B, FTDI_RXFBSW_B, FTDI_RXTDD_MODE_B, FTDI_TXTDD_MODE_B, FTDI_RXFBNCO_B, FTDI_RXDSAFAST_B
AFE2_FTDI_SPI: FTDI_FSPICLKA_B, FTDI_FSPIDA_B, FTDI_FSPICLKB_B, FTDI_FSPIDB_B, FTDI_FSPICLKC_B, FTDI_FSPIDC_B, FTDI_FSPICLKD_B, FTDI_FSPIDD_B, FTDI_SPIASEN_B, FTDI_SPIACLK_B, FTDI_SPIASDO_B, FTDI_SPIASDIO_B, FTDI_SPIBSEN_B, FTDI_SPIBCLK_B, FTDI_SPIBSDO_B, FTDI_SPIBSDIO_B
AFE2_SERDES: ADC_DB0_N, ADC_DB0_P, ADC_DB1_N, ADC_DB1_P, ADC_DB2_N, ADC_DB2_P, ADC_DB3_N, ADC_DB3_P, ADC_DB4_N, ADC_DB4_P, ADC_DB5_N, ADC_DB5_P, ADC_DB6_N, ADC_DB6_P, ADC_DB7_N, ADC_DB7_P, DAC_DB0_N, DAC_DB0_P, DAC_DB1_N, DAC_DB1_P, DAC_DB2_N, DAC_DB2_P, DAC_DB3_N, DAC_DB3_P, DAC_DB4_N, DAC_DB4_P, DAC_DB5_N, DAC_DB5_P, DAC_DB6_N, DAC_DB6_P, DAC_DB7_N, DAC_DB7_P
AFE2_MISC: AFE2_ADC_ALT_SYNC_N, AFE2_ADC_ALT_SYNC_P, AFE2_ADC_SYNC_N, AFE2_ADC_SYNC_P, AFE2_DAC_ALT_SYNC_N, AFE2_DAC_ALT_SYNC_P, AFE2_DAC_SYNC_N, AFE2_DAC_SYNC_P, AFE2_FMC_FSPICLKA, AFE2_FMC_FSPICLKB, AFE2_FMC_FSPICLKC, AFE2_FMC_FSPICLKD, AFE2_FMC_FSPIDA, AFE2_FMC_FSPIDB, AFE2_FMC_FSPIDC, AFE2_FMC_FSPIDD, AFE2_FMC_RXADSA1PD, AFE2_FMC_RXADSA2PD, AFE2_FMC_RXADSAFAST, AFE2_FMC_RXAPD2H, AFE2_FMC_RXAPD2L, AFE2_FMC_RXBDSA1PD, AFE2_FMC_RXBDSA2PD, AFE2_FMC_RXBDSAFAST, AFE2_FMC_RXBPD2H, AFE2_FMC_RXBPD2L, AFE2_FMC_RXDSASW, AFE2_FMC_TXDSASW, AFE2_FMC_TXTDD1, AFE2_FMC_TXTDD2, AFE2_syncb0cmos, AFE2_syncb1cmos, AFE2_syncb2cmos, AFE2_syncb3cmos
FTDI_JTAG: FTDI_TCK, FTDI_TDI, FTDI_TDO, FTDI_TMS, FTDI_TRSTB
AFE2_FMC_SPI: AFE2_FMC_SPIACLK, AFE2_FMC_SPIASDIO, AFE2_FMC_SPIASDO, AFE2_FMC_SPIASEN, AFE2_FMC_SPIBCLK, AFE2_FMC_SPIBSDIO, AFE2_FMC_SPIBSDO, AFE2_FMC_SPIBSEN

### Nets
ADC_DB0_N: sheet AFE2-SERDES/DP0_M2C_N, port AFE2_SERDES.ADC_DB0_N
ADC_DB0_P: sheet AFE2-SERDES/DP0_M2C_P, port AFE2_SERDES.ADC_DB0_P
ADC_DB1_N: sheet AFE2-SERDES/DP1_M2C_N, port AFE2_SERDES.ADC_DB1_N
ADC_DB1_P: sheet AFE2-SERDES/DP1_M2C_P, port AFE2_SERDES.ADC_DB1_P
ADC_DB2_N: sheet AFE2-SERDES/DP2_M2C_N, port AFE2_SERDES.ADC_DB2_N
ADC_DB2_P: sheet AFE2-SERDES/DP2_M2C_P, port AFE2_SERDES.ADC_DB2_P
ADC_DB3_N: sheet AFE2-SERDES/DP3_M2C_N, port AFE2_SERDES.ADC_DB3_N
ADC_DB3_P: sheet AFE2-SERDES/DP3_M2C_P, port AFE2_SERDES.ADC_DB3_P
ADC_DB4_N: sheet AFE2-SERDES/DP4_M2C_N, port AFE2_SERDES.ADC_DB4_N
ADC_DB4_P: sheet AFE2-SERDES/DP4_M2C_P, port AFE2_SERDES.ADC_DB4_P
ADC_DB5_N: sheet AFE2-SERDES/DP5_M2C_N, port AFE2_SERDES.ADC_DB5_N
ADC_DB5_P: sheet AFE2-SERDES/DP5_M2C_P, port AFE2_SERDES.ADC_DB5_P
ADC_DB6_N: sheet AFE2-SERDES/DP6_M2C_N, port AFE2_SERDES.ADC_DB6_N
ADC_DB6_P: sheet AFE2-SERDES/DP6_M2C_P, port AFE2_SERDES.ADC_DB6_P
ADC_DB7_N: sheet AFE2-SERDES/DP7_M2C_N, port AFE2_SERDES.ADC_DB7_N
ADC_DB7_P: sheet AFE2-SERDES/DP7_M2C_P, port AFE2_SERDES.ADC_DB7_P
AFE1_DCO: port AFE1_DCO, sheet AFE2-RX-INPUTS/AFE1_DCO
AFE2_ADC_ALT_SYNC_N: sheet AFE2-PROGRAMMING INTERFACE/ADC_ALT_SYNC_N, port AFE2_MISC.AFE2_ADC_ALT_SYNC_N
AFE2_ADC_ALT_SYNC_P: sheet AFE2-PROGRAMMING INTERFACE/ADC_ALT_SYNC_P, port AFE2_MISC.AFE2_ADC_ALT_SYNC_P
AFE2_ADC_SYNC_N: sheet AFE2-PROGRAMMING INTERFACE/ADC_SYNC_N, port AFE2_MISC.AFE2_ADC_SYNC_N
AFE2_ADC_SYNC_P: sheet AFE2-PROGRAMMING INTERFACE/ADC_SYNC_P, port AFE2_MISC.AFE2_ADC_SYNC_P
AFE2_DAC_ALT_SYNC_N: sheet AFE2-PROGRAMMING INTERFACE/DAC_ALT_SYNC_N, port AFE2_MISC.AFE2_DAC_ALT_SYNC_N
AFE2_DAC_ALT_SYNC_P: sheet AFE2-PROGRAMMING INTERFACE/DAC_ALT_SYNC_P, port AFE2_MISC.AFE2_DAC_ALT_SYNC_P
AFE2_DAC_SYNC_N: sheet AFE2-PROGRAMMING INTERFACE/DAC_SYNC_N, port AFE2_MISC.AFE2_DAC_SYNC_N
AFE2_DAC_SYNC_P: sheet AFE2-PROGRAMMING INTERFACE/DAC_SYNC_P, port AFE2_MISC.AFE2_DAC_SYNC_P
AFE2_DCLK: port AFE2_DCLK, sheet AFE2-RX-TX-INTERFACE/AFE2_DCLK
AFE2_DCO: port AFE2_DCO, sheet AFE2-TX-OUTPUTS/AFE2_DCO
AFE2_DIV_IN: port AFE2_DIV_IN, sheet AFE2-RX-TX-INTERFACE/AFE2_DIV_IN
AFE2_FMC_FSPICLKA: sheet AFE2-PROGRAMMING INTERFACE/FMC_FSPICLKA, port AFE2_MISC.AFE2_FMC_FSPICLKA
AFE2_FMC_FSPICLKB: sheet AFE2-PROGRAMMING INTERFACE/FMC_FSPICLKB, port AFE2_MISC.AFE2_FMC_FSPICLKB
AFE2_FMC_FSPICLKC: sheet AFE2-PROGRAMMING INTERFACE/FMC_FSPICLKC, port AFE2_MISC.AFE2_FMC_FSPICLKC
AFE2_FMC_FSPICLKD: sheet AFE2-PROGRAMMING INTERFACE/FMC_FSPICLKD, port AFE2_MISC.AFE2_FMC_FSPICLKD
AFE2_FMC_FSPIDA: sheet AFE2-PROGRAMMING INTERFACE/FMC_FSPIDA, port AFE2_MISC.AFE2_FMC_FSPIDA
AFE2_FMC_FSPIDB: sheet AFE2-PROGRAMMING INTERFACE/FMC_FSPIDB, port AFE2_MISC.AFE2_FMC_FSPIDB
AFE2_FMC_FSPIDC: sheet AFE2-PROGRAMMING INTERFACE/FMC_FSPIDC, port AFE2_MISC.AFE2_FMC_FSPIDC
AFE2_FMC_FSPIDD: sheet AFE2-PROGRAMMING INTERFACE/FMC_FSPIDD, port AFE2_MISC.AFE2_FMC_FSPIDD
AFE2_FMC_RXADSA1PD: sheet AFE2-GPIOs/FMC_RXADSA1PD, port AFE2_MISC.AFE2_FMC_RXADSA1PD
AFE2_FMC_RXADSA2PD: sheet AFE2-GPIOs/FMC_RXADSA2PD, port AFE2_MISC.AFE2_FMC_RXADSA2PD
AFE2_FMC_RXADSAFAST: sheet AFE2-GPIOs/FMC_RXADSAFAST, port AFE2_MISC.AFE2_FMC_RXADSAFAST
AFE2_FMC_RXAPD2H: sheet AFE2-GPIOs/FMC_RXAPD2H, port AFE2_MISC.AFE2_FMC_RXAPD2H
AFE2_FMC_RXAPD2L: sheet AFE2-GPIOs/FMC_RXAPD2L, port AFE2_MISC.AFE2_FMC_RXAPD2L
AFE2_FMC_RXBDSA1PD: sheet AFE2-GPIOs/FMC_RXBDSA1PD, port AFE2_MISC.AFE2_FMC_RXBDSA1PD
AFE2_FMC_RXBDSA2PD: sheet AFE2-GPIOs/FMC_RXBDSA2PD, port AFE2_MISC.AFE2_FMC_RXBDSA2PD
AFE2_FMC_RXBDSAFAST: sheet AFE2-GPIOs/FMC_RXBDSAFAST, port AFE2_MISC.AFE2_FMC_RXBDSAFAST
AFE2_FMC_RXBPD2H: sheet AFE2-GPIOs/FMC_RXBPD2H, port AFE2_MISC.AFE2_FMC_RXBPD2H
AFE2_FMC_RXBPD2L: sheet AFE2-GPIOs/FMC_RXBPD2L, port AFE2_MISC.AFE2_FMC_RXBPD2L
AFE2_FMC_RXDSASW: sheet AFE2-GPIOs/FMC_RXDSASW, port AFE2_MISC.AFE2_FMC_RXDSASW
AFE2_FMC_SPIACLK: sheet AFE2-PROGRAMMING INTERFACE/FMC_SPIACLK, port AFE2_FMC_SPI.AFE2_FMC_SPIACLK
AFE2_FMC_SPIASDIO: sheet AFE2-PROGRAMMING INTERFACE/FMC_SPIASDIO, port AFE2_FMC_SPI.AFE2_FMC_SPIASDIO
AFE2_FMC_SPIASDO: sheet AFE2-PROGRAMMING INTERFACE/FMC_SPIASDO, port AFE2_FMC_SPI.AFE2_FMC_SPIASDO
AFE2_FMC_SPIASEN: sheet AFE2-PROGRAMMING INTERFACE/FMC_SPIASEN, port AFE2_FMC_SPI.AFE2_FMC_SPIASEN
AFE2_FMC_SPIBCLK: sheet AFE2-PROGRAMMING INTERFACE/FMC_SPIBCLK, port AFE2_FMC_SPI.AFE2_FMC_SPIBCLK
AFE2_FMC_SPIBSDIO: sheet AFE2-PROGRAMMING INTERFACE/FMC_SPIBSDIO, port AFE2_FMC_SPI.AFE2_FMC_SPIBSDIO
AFE2_FMC_SPIBSDO: sheet AFE2-PROGRAMMING INTERFACE/FMC_SPIBSDO, port AFE2_FMC_SPI.AFE2_FMC_SPIBSDO
AFE2_FMC_SPIBSEN: sheet AFE2-PROGRAMMING INTERFACE/FMC_SPIBSEN, port AFE2_FMC_SPI.AFE2_FMC_SPIBSEN
AFE2_FMC_TXDSASW: sheet AFE2-GPIOs/FMC_TXDSASW, port AFE2_MISC.AFE2_FMC_TXDSASW
AFE2_FMC_TXTDD1: sheet AFE2-GPIOs/FMC_TXTDD1, port AFE2_MISC.AFE2_FMC_TXTDD1
AFE2_FMC_TXTDD2: sheet AFE2-GPIOs/FMC_TXTDD2, port AFE2_MISC.AFE2_FMC_TXTDD2
AFE2_syncb0cmos: sheet AFE2-PROGRAMMING INTERFACE/syncb0cmos, port AFE2_MISC.AFE2_syncb0cmos
AFE2_syncb1cmos: sheet AFE2-PROGRAMMING INTERFACE/syncb1cmos, port AFE2_MISC.AFE2_syncb1cmos
AFE2_syncb2cmos: sheet AFE2-PROGRAMMING INTERFACE/syncb2cmos, port AFE2_MISC.AFE2_syncb2cmos
AFE2_syncb3cmos: sheet AFE2-PROGRAMMING INTERFACE/syncb3cmos, port AFE2_MISC.AFE2_syncb3cmos
DAC_DB0_N: sheet AFE2-SERDES/DP0_C2M_N, port AFE2_SERDES.DAC_DB0_N
DAC_DB0_P: sheet AFE2-SERDES/DP0_C2M_P, port AFE2_SERDES.DAC_DB0_P
DAC_DB1_N: sheet AFE2-SERDES/DP1_C2M_N, port AFE2_SERDES.DAC_DB1_N
DAC_DB1_P: sheet AFE2-SERDES/DP1_C2M_P, port AFE2_SERDES.DAC_DB1_P
DAC_DB2_N: sheet AFE2-SERDES/DP2_C2M_N, port AFE2_SERDES.DAC_DB2_N
DAC_DB2_P: sheet AFE2-SERDES/DP2_C2M_P, port AFE2_SERDES.DAC_DB2_P
DAC_DB3_N: sheet AFE2-SERDES/DP3_C2M_N, port AFE2_SERDES.DAC_DB3_N
DAC_DB3_P: sheet AFE2-SERDES/DP3_C2M_P, port AFE2_SERDES.DAC_DB3_P
DAC_DB4_N: sheet AFE2-SERDES/DP4_C2M_N, port AFE2_SERDES.DAC_DB4_N
DAC_DB4_P: sheet AFE2-SERDES/DP4_C2M_P, port AFE2_SERDES.DAC_DB4_P
DAC_DB5_N: sheet AFE2-SERDES/DP5_C2M_N, port AFE2_SERDES.DAC_DB5_N
DAC_DB5_P: sheet AFE2-SERDES/DP5_C2M_P, port AFE2_SERDES.DAC_DB5_P
DAC_DB6_N: sheet AFE2-SERDES/DP6_C2M_N, port AFE2_SERDES.DAC_DB6_N
DAC_DB6_P: sheet AFE2-SERDES/DP6_C2M_P, port AFE2_SERDES.DAC_DB6_P
DAC_DB7_N: sheet AFE2-SERDES/DP7_C2M_N, port AFE2_SERDES.DAC_DB7_N
DAC_DB7_P: sheet AFE2-SERDES/DP7_C2M_P, port AFE2_SERDES.DAC_DB7_P
DACOUT: port DACOUT, sheet AFE2-GPIOs/DACOUT
FMC_TCK: sheet AFE2-PROGRAMMING INTERFACE/FMC_TCK, port FMC_JTAG.FMC_TCK
FMC_TDI: port FMC_TDI, sheet AFE2-PROGRAMMING INTERFACE/FMC_TDI
FMC_TDO: sheet AFE2-PROGRAMMING INTERFACE/FMC_TDO, port FMC_JTAG.FMC_TDO
FMC_TMS: sheet AFE2-PROGRAMMING INTERFACE/FMC_TMS, port FMC_JTAG.FMC_TMS
FMC_TRSTB: sheet AFE2-PROGRAMMING INTERFACE/FMC_TRSTB, port FMC_JTAG.FMC_TRSTB
FTDI_DSASW_B: sheet AFE2-GPIOs/FTDI_DSASW_B, port AFE2_FTDI_GPIO.FTDI_DSASW_B
FTDI_FBBANDSEL_B: sheet AFE2-GPIOs/FTDI_FBBANDSEL_B, port AFE2_FTDI_GPIO.FTDI_FBBANDSEL_B
FTDI_FSPICLKA_B: sheet AFE2-PROGRAMMING INTERFACE/FTDI_FSPICLKA, port AFE2_FTDI_SPI.FTDI_FSPICLKA_B
FTDI_FSPICLKB: sheet AFE2-PROGRAMMING INTERFACE/FTDI_FSPICLKB, port AFE2_FTDI_SPI.FTDI_FSPICLKB_B
FTDI_FSPICLKC_B: sheet AFE2-PROGRAMMING INTERFACE/FTDI_FSPICLKC, port AFE2_FTDI_SPI.FTDI_FSPICLKC_B
FTDI_FSPICLKD_B: sheet AFE2-PROGRAMMING INTERFACE/FTDI_FSPICLKD, port AFE2_FTDI_SPI.FTDI_FSPICLKD_B
FTDI_FSPIDA_B: sheet AFE2-PROGRAMMING INTERFACE/FTDI_FSPIDA, port AFE2_FTDI_SPI.FTDI_FSPIDA_B
FTDI_FSPIDB_B: sheet AFE2-PROGRAMMING INTERFACE/FTDI_FSPIDB, port AFE2_FTDI_SPI.FTDI_FSPIDB_B
FTDI_FSPIDC_B: sheet AFE2-PROGRAMMING INTERFACE/FTDI_FSPIDC, port AFE2_FTDI_SPI.FTDI_FSPIDC_B
FTDI_FSPIDD_B: sheet AFE2-PROGRAMMING INTERFACE/FTDI_FSPIDD, port AFE2_FTDI_SPI.FTDI_FSPIDD_B
FTDI_RXDSAFAST_B: sheet AFE2-GPIOs/FTDI_RXDSAFAST_B, port AFE2_FTDI_GPIO.FTDI_RXDSAFAST_B
FTDI_RXFBNCO_B: sheet AFE2-GPIOs/FTDI_RXFBNCO_B, port AFE2_FTDI_GPIO.FTDI_RXFBNCO_B
FTDI_RXFBSW_B: sheet AFE2-GPIOs/FTDI_RXFBSW_B, port AFE2_FTDI_GPIO.FTDI_RXFBSW_B
FTDI_RXTDD_MODE_B: sheet AFE2-GPIOs/FTDI_RXTDD_MODE_B, port AFE2_FTDI_GPIO.FTDI_RXTDD_MODE_B
FTDI_SPIACLK_B: sheet AFE2-PROGRAMMING INTERFACE/FTDI_SPIACLK, port AFE2_FTDI_SPI.FTDI_SPIACLK_B
FTDI_SPIASDIO_B: sheet AFE2-PROGRAMMING INTERFACE/FTDI_SPIASDIO, port AFE2_FTDI_SPI.FTDI_SPIASDIO_B
FTDI_SPIASDO_B: sheet AFE2-PROGRAMMING INTERFACE/FTDI_SPIASDO, port AFE2_FTDI_SPI.FTDI_SPIASDO_B
FTDI_SPIASEN_B: sheet AFE2-PROGRAMMING INTERFACE/FTDI_SPIASEN, port AFE2_FTDI_SPI.FTDI_SPIASEN_B
FTDI_SPIBCLK_B: sheet AFE2-PROGRAMMING INTERFACE/FTDI_SPIBCLK, port AFE2_FTDI_SPI.FTDI_SPIBCLK_B
FTDI_SPIBSDIO_B: sheet AFE2-PROGRAMMING INTERFACE/FTDI_SPIBSDIO, port AFE2_FTDI_SPI.FTDI_SPIBSDIO_B
FTDI_SPIBSDO_B: sheet AFE2-PROGRAMMING INTERFACE/FTDI_SPIBSDO, port AFE2_FTDI_SPI.FTDI_SPIBSDO_B
FTDI_SPIBSEN_B: sheet AFE2-PROGRAMMING INTERFACE/FTDI_SPIBSEN, port AFE2_FTDI_SPI.FTDI_SPIBSEN_B
FTDI_TCK: sheet AFE2-PROGRAMMING INTERFACE/FTDI_TCK, port FTDI_JTAG.FTDI_TCK
FTDI_TDI: port FTDI_TDI, sheet AFE2-PROGRAMMING INTERFACE/FTDI_TDI
FTDI_TDO: sheet AFE2-PROGRAMMING INTERFACE/FTDI_TDO, port FTDI_JTAG.FTDI_TDO
FTDI_TMS: sheet AFE2-PROGRAMMING INTERFACE/FTDI_TMS, port FTDI_JTAG.FTDI_TMS
FTDI_TRSTB: sheet AFE2-PROGRAMMING INTERFACE/FTDI_TRSTB, port FTDI_JTAG.FTDI_TRSTB
FTDI_TXTDD_MODE_B: sheet AFE2-GPIOs/FTDI_TXTDD_MODE_B, port AFE2_FTDI_GPIO.FTDI_TXTDD_MODE_B
LMK_AFE2_CLKM: port LMK_AFE2_CLKM, sheet AFE2-LMX2594/LMK_AFE2_CLKM, sheet AFE2-RX-TX-INTERFACE/LMK_AFE2_CLKM
LMK_AFE2_CLKP: port LMK_AFE2_CLKP, sheet AFE2-LMX2594/LMK_AFE2_CLKP, sheet AFE2-RX-TX-INTERFACE/LMK_AFE2_CLKP
LMK_AFE2_SYSREFM: port LMK_AFE2_SYSREFM, sheet AFE2-LMX2594/LMK_AFE2_SYSREFM, sheet AFE2-RX-TX-INTERFACE/LMK_AFE2_SYSREFM
LMK_AFE2_SYSREFP: port LMK_AFE2_SYSREFP, sheet AFE2-LMX2594/LMK_AFE2_SYSREFP, sheet AFE2-RX-TX-INTERFACE/LMK_AFE2_SYSREFP
LMX2_REFN: port LMX2_REFN, sheet AFE2-LMX2594/LMX2_REFN
LMX2_REFP: port LMX2_REFP, sheet AFE2-LMX2594/LMX2_REFP
LMX2_SDO: port LMX2_SDO, sheet AFE2-LMX2594/LMX2_SDO
LMX_CS: port LMX_CS, sheet AFE2-LMX2594/LMX_CS
LMX_SCK: port LMX_SCK, sheet AFE2-LMX2594/LMX_SCK
LMX_SDIO: port LMX_SDIO, sheet AFE2-LMX2594/LMX_SDIO
SDCLKout13_N: port SDCLKout13_N, sheet AFE2-LMX2594/SDCLKout13_N
SDCLKout13_P: port SDCLKout13_P, sheet AFE2-LMX2594/SDCLKout13_P
(unnamed): sheet AFE2-RX-INPUTS/AFE2_CIN1M, sheet AFE2-RX-TX-INTERFACE/AFE2_CIN1M
(unnamed): sheet AFE2-RX-INPUTS/AFE2_BIN2P, sheet AFE2-RX-TX-INTERFACE/AFE2_BIN2P  [a separate net that carries the same name]
(unnamed): sheet AFE2-RX-INPUTS/AFE2_AIN2P, sheet AFE2-RX-TX-INTERFACE/AFE2_AIN2P  [a separate net that carries the same name]
(unnamed): sheet AFE2-RX-INPUTS/AFE2_DIN2P, sheet AFE2-RX-TX-INTERFACE/AFE2_DIN2P  [a separate net that carries the same name]
(unnamed): sheet AFE2-RX-INPUTS/AFE2_BIN2M, sheet AFE2-RX-TX-INTERFACE/AFE2_BIN2M  [a separate net that carries the same name]
(unnamed): sheet AFE2-RX-INPUTS/AFE2_CIN1P, sheet AFE2-RX-TX-INTERFACE/AFE2_CIN1P  [a separate net that carries the same name]
(unnamed): sheet AFE2-RX-INPUTS/AFE2_DIN2M, sheet AFE2-RX-TX-INTERFACE/AFE2_DIN2M  [a separate net that carries the same name]
(unnamed): sheet AFE2-RX-INPUTS/AFE2_AIN1M, sheet AFE2-RX-TX-INTERFACE/AFE2_AIN1M  [a separate net that carries the same name]
(unnamed): sheet AFE2-RX-INPUTS/AFE2_DIN1P, sheet AFE2-RX-TX-INTERFACE/AFE2_DIN1P  [a separate net that carries the same name]
(unnamed): sheet AFE2-RX-INPUTS/AFE2_BIN1M, sheet AFE2-RX-TX-INTERFACE/AFE2_BIN1M  [a separate net that carries the same name]
(unnamed): sheet AFE2-RX-INPUTS/AFE2_AIN2M, sheet AFE2-RX-TX-INTERFACE/AFE2_AIN2M  [a separate net that carries the same name]
(unnamed): sheet AFE2-RX-INPUTS/AFE2_DIN1M, sheet AFE2-RX-TX-INTERFACE/AFE2_DIN1M  [a separate net that carries the same name]
(unnamed): sheet AFE2-RX-INPUTS/AFE2_CIN2P, sheet AFE2-RX-TX-INTERFACE/AFE2_CIN2P  [a separate net that carries the same name]
(unnamed): sheet AFE2-RX-INPUTS/AFE2_CIN2M, sheet AFE2-RX-TX-INTERFACE/AFE2_CIN2M  [a separate net that carries the same name]
(unnamed): sheet AFE2-RX-INPUTS/AFE2_AIN1P, sheet AFE2-RX-TX-INTERFACE/AFE2_AIN1P  [a separate net that carries the same name]
(unnamed): sheet AFE2-RX-INPUTS/AFE2_BIN1P, sheet AFE2-RX-TX-INTERFACE/AFE2_BIN1P  [a separate net that carries the same name]
(unnamed): sheet AFE2-TX-OUTPUTS/AFE2_TXAM, sheet AFE2-RX-TX-INTERFACE/AFE2_TXAM  [a separate net that carries the same name]
(unnamed): sheet AFE2-TX-OUTPUTS/AFE2_TXAP, sheet AFE2-RX-TX-INTERFACE/AFE2_TXAP  [a separate net that carries the same name]
(unnamed): sheet AFE2-TX-OUTPUTS/AFE2_TXDBM, sheet AFE2-RX-TX-INTERFACE/AFE2_TXBM  [a separate net that carries the same name]
(unnamed): sheet AFE2-TX-OUTPUTS/AFE2_TXDBP, sheet AFE2-RX-TX-INTERFACE/AFE2_TXBP  [a separate net that carries the same name]
(unnamed): sheet AFE2-TX-OUTPUTS/AFE2_TXCM, sheet AFE2-RX-TX-INTERFACE/AFE2_TXCM  [a separate net that carries the same name]
(unnamed): sheet AFE2-TX-OUTPUTS/AFE2_TXCP, sheet AFE2-RX-TX-INTERFACE/AFE2_TXCP  [a separate net that carries the same name]
(unnamed): sheet AFE2-TX-OUTPUTS/AFE2_TXDM, sheet AFE2-RX-TX-INTERFACE/AFE2_TXDM  [a separate net that carries the same name]
(unnamed): sheet AFE2-TX-OUTPUTS/AFE2_TXDP, sheet AFE2-RX-TX-INTERFACE/AFE2_TXDP  [a separate net that carries the same name]
(unnamed): sheet AFE2-LMX2594/AFE2_CLKP, sheet AFE2-RX-TX-INTERFACE/AFE2_CLKP  [a separate net that carries the same name]
(unnamed): sheet AFE2-LMX2594/AFE2_CLKN, sheet AFE2-RX-TX-INTERFACE/AFE2_CLKN  [a separate net that carries the same name]
(unnamed): sheet AFE2-LMX2594/AFE2_SYSREFP, sheet AFE2-RX-TX-INTERFACE/AFE2_SYSREFP  [a separate net that carries the same name]
(unnamed): sheet AFE2-LMX2594/AFE2_SYSREFN, sheet AFE2-RX-TX-INTERFACE/AFE2_SYSREFN  [a separate net that carries the same name]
